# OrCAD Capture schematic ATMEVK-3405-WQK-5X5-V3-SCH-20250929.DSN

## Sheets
1 10. VDDIO-VCCIO Tracking: size B; title: ATM3405 EVALUATION BOARD; rev: 3; note: 085-37-510-xxxx
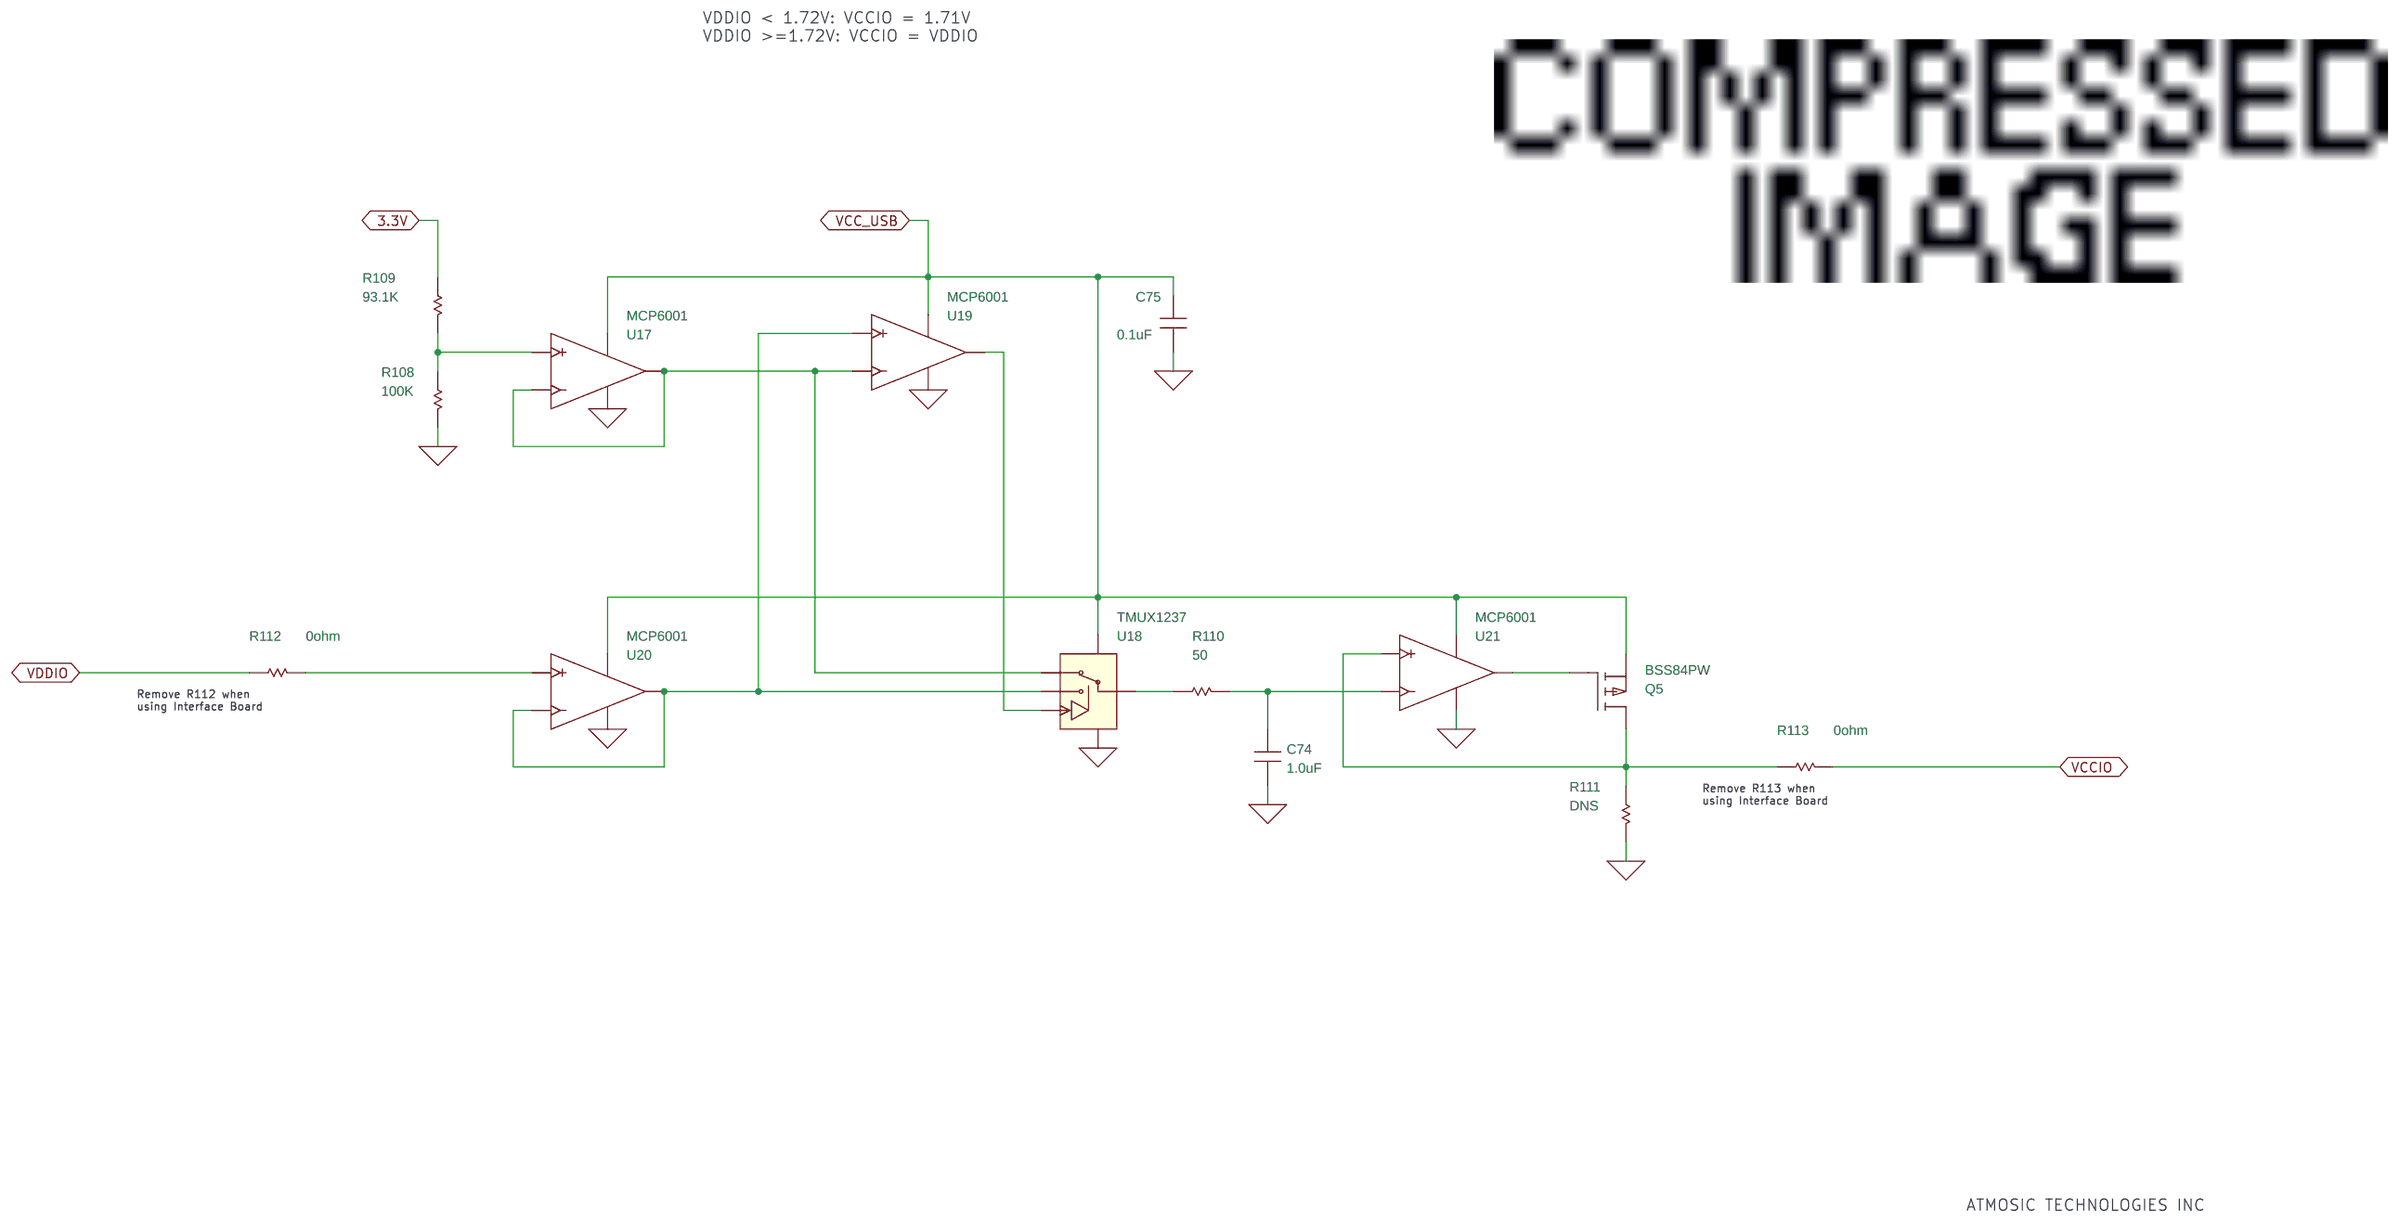
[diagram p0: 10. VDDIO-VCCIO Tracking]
2 01. TITLE
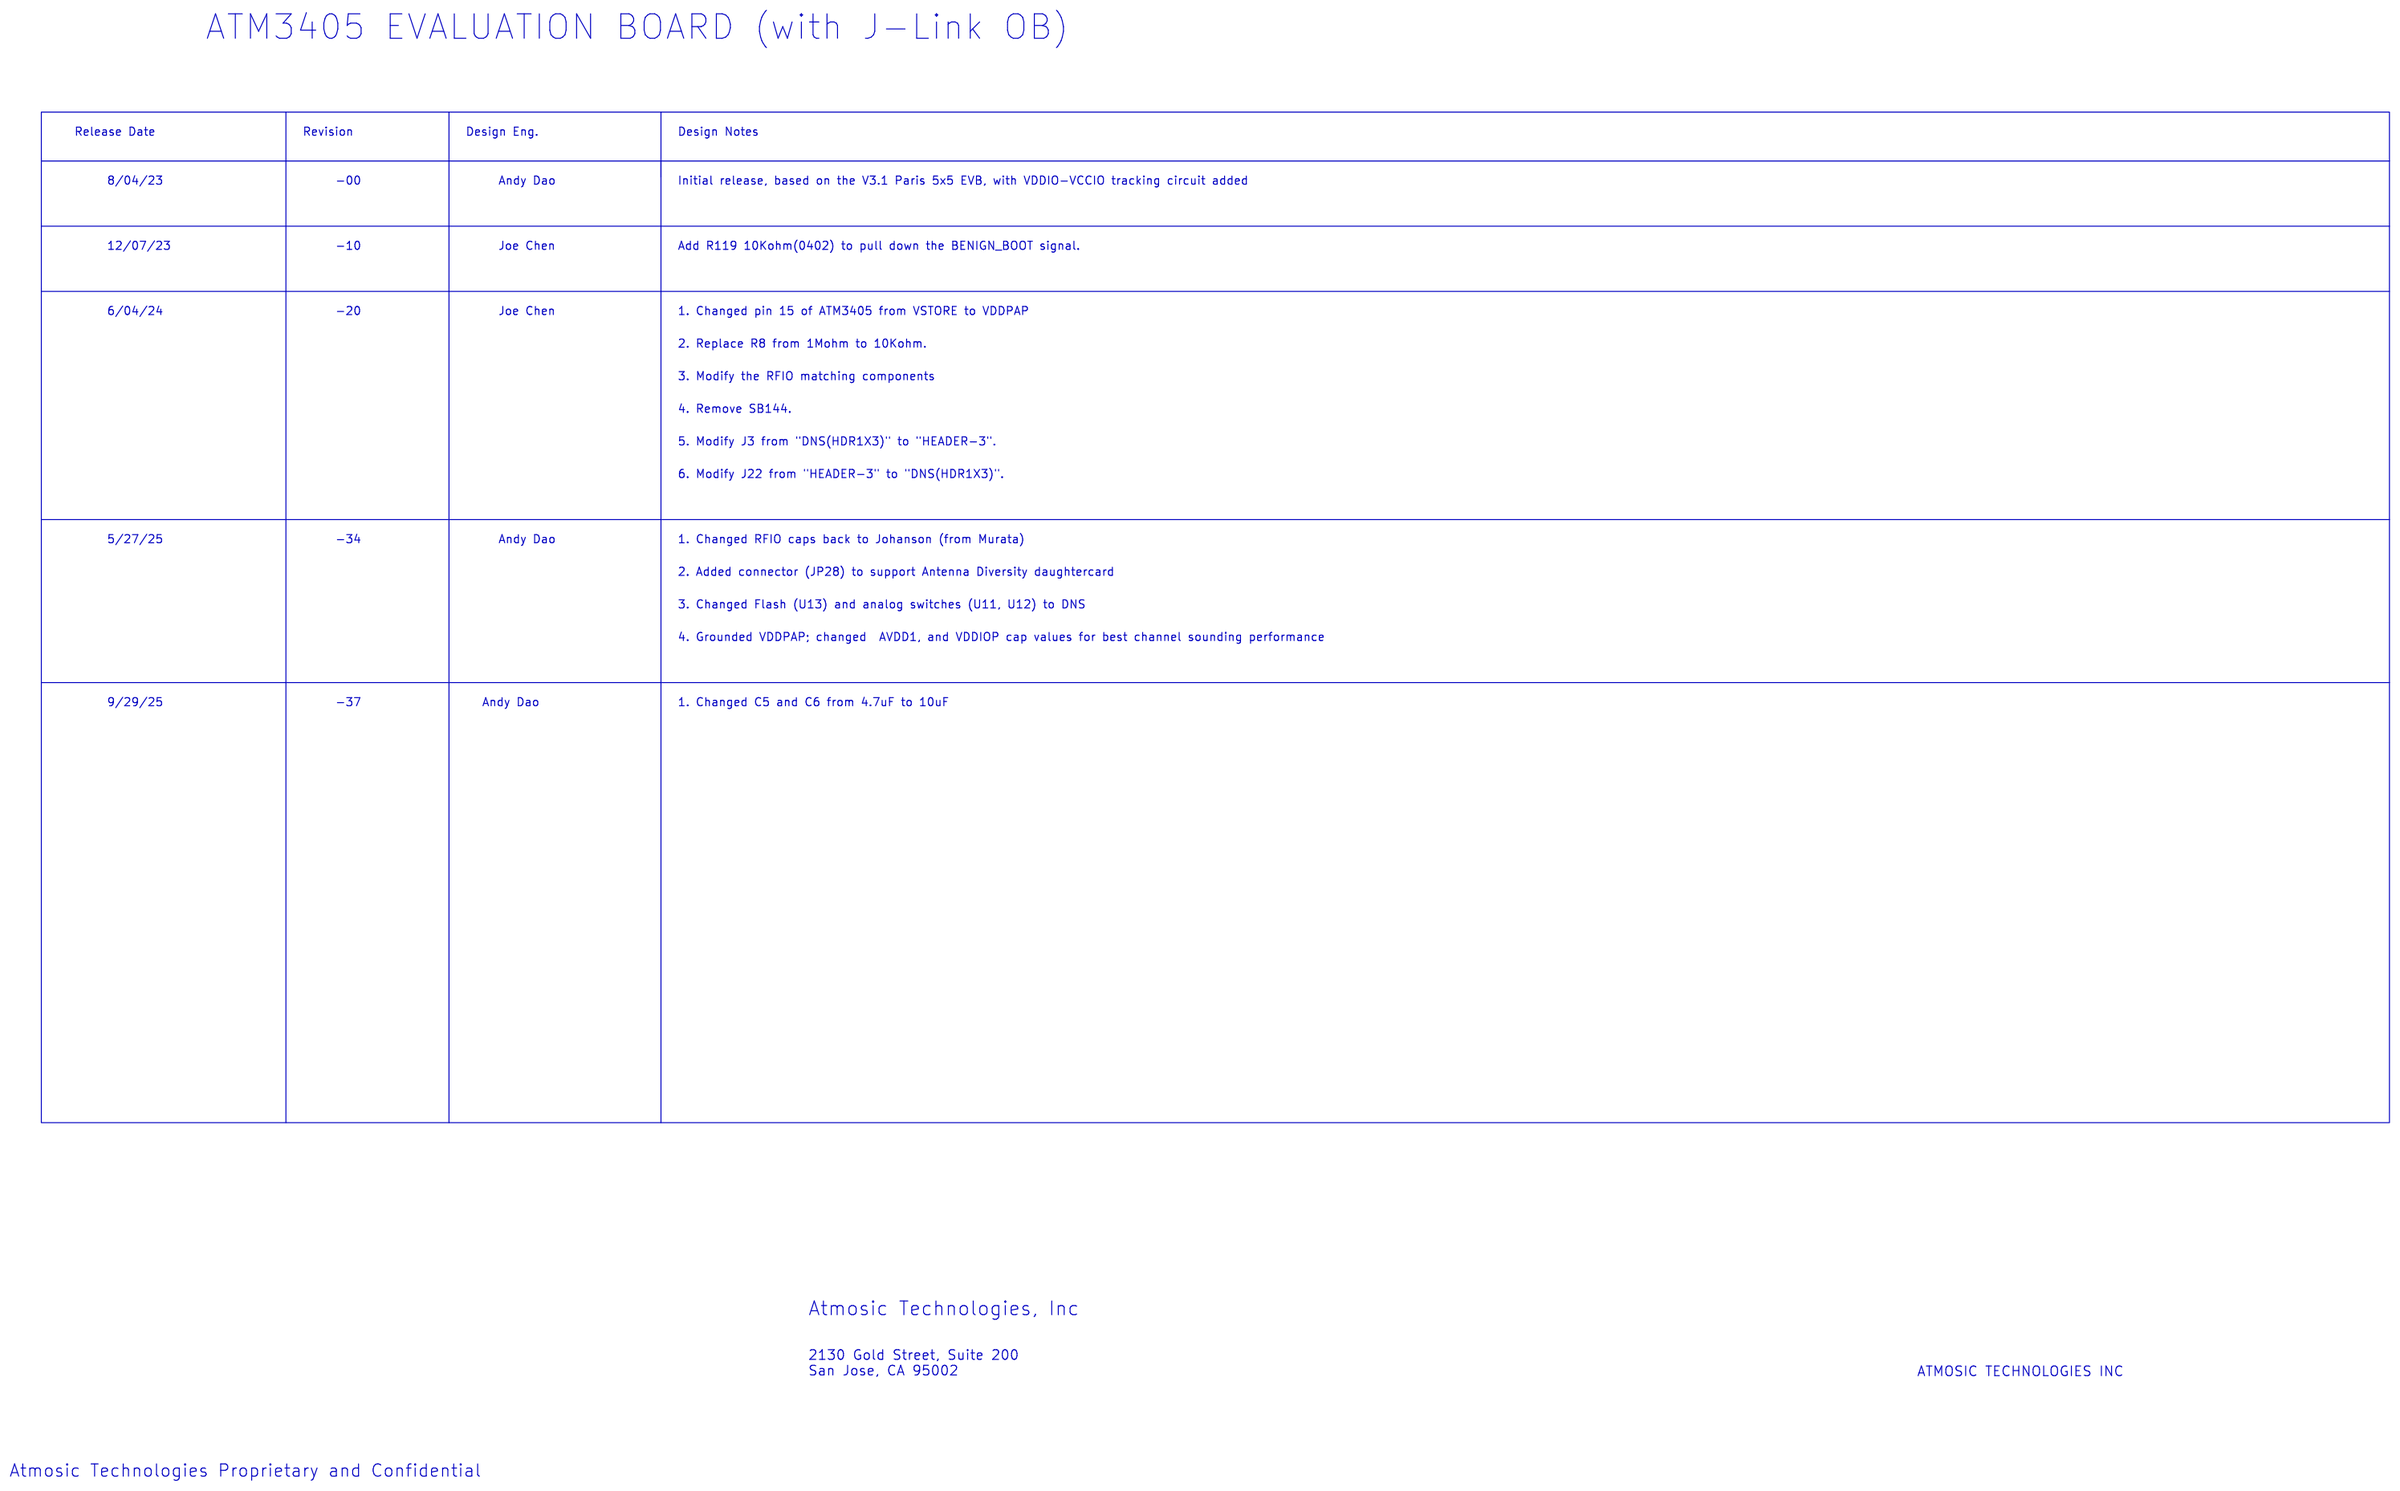
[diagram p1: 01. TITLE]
3 02. Block Diagram
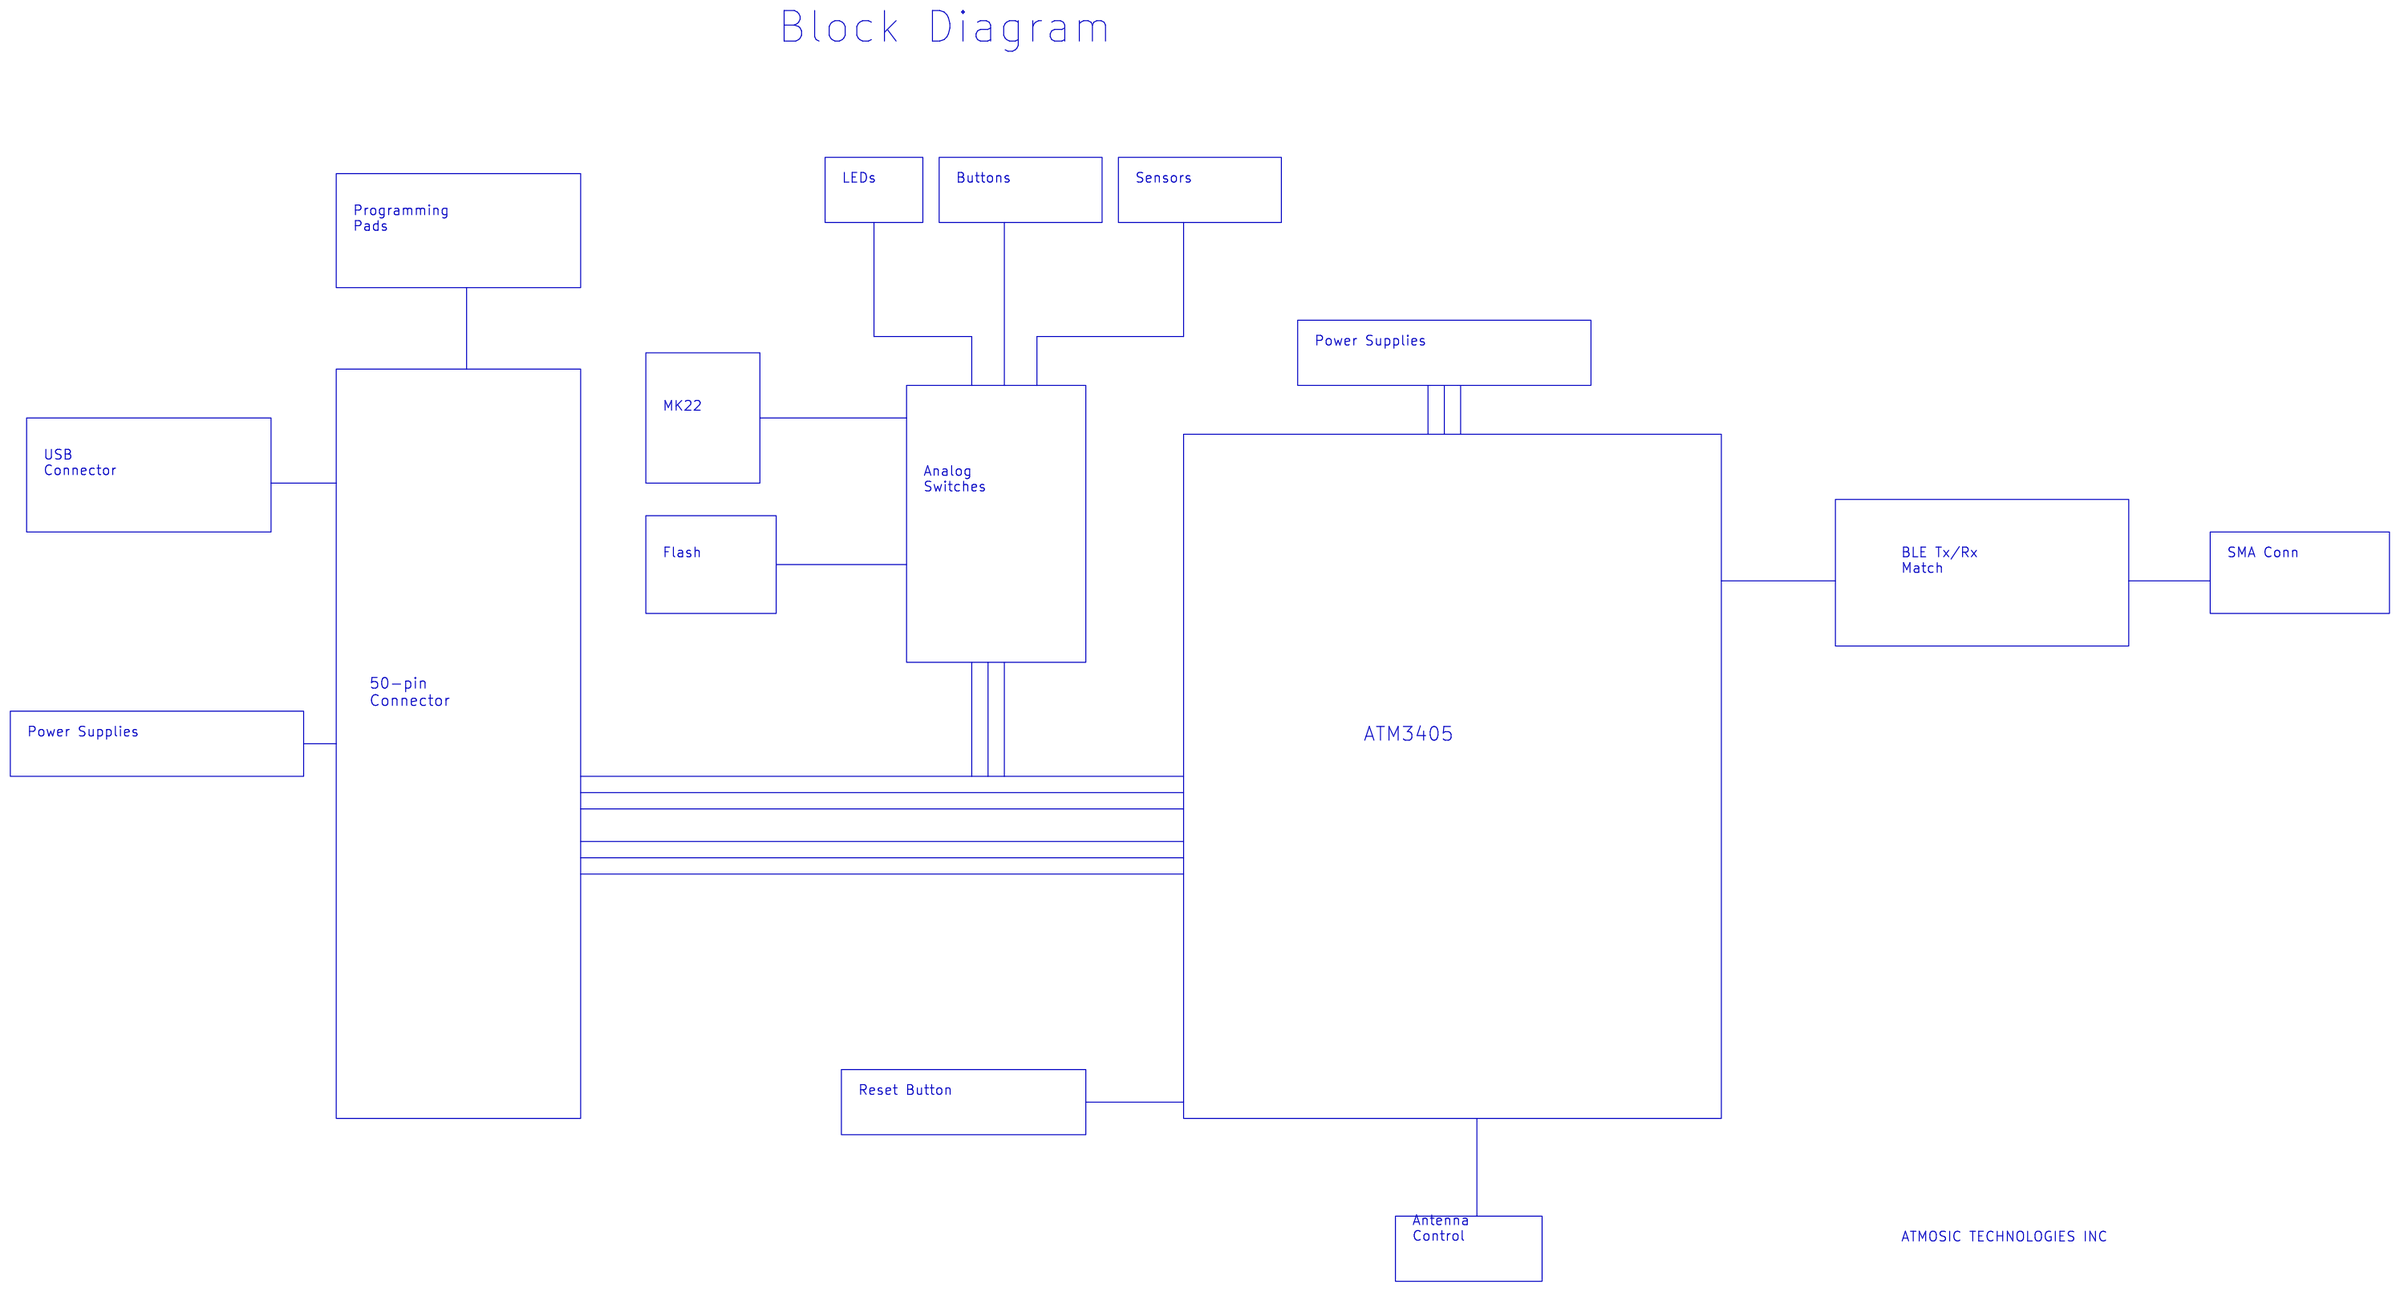
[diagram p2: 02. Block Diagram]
4 03. ATM3405: size B
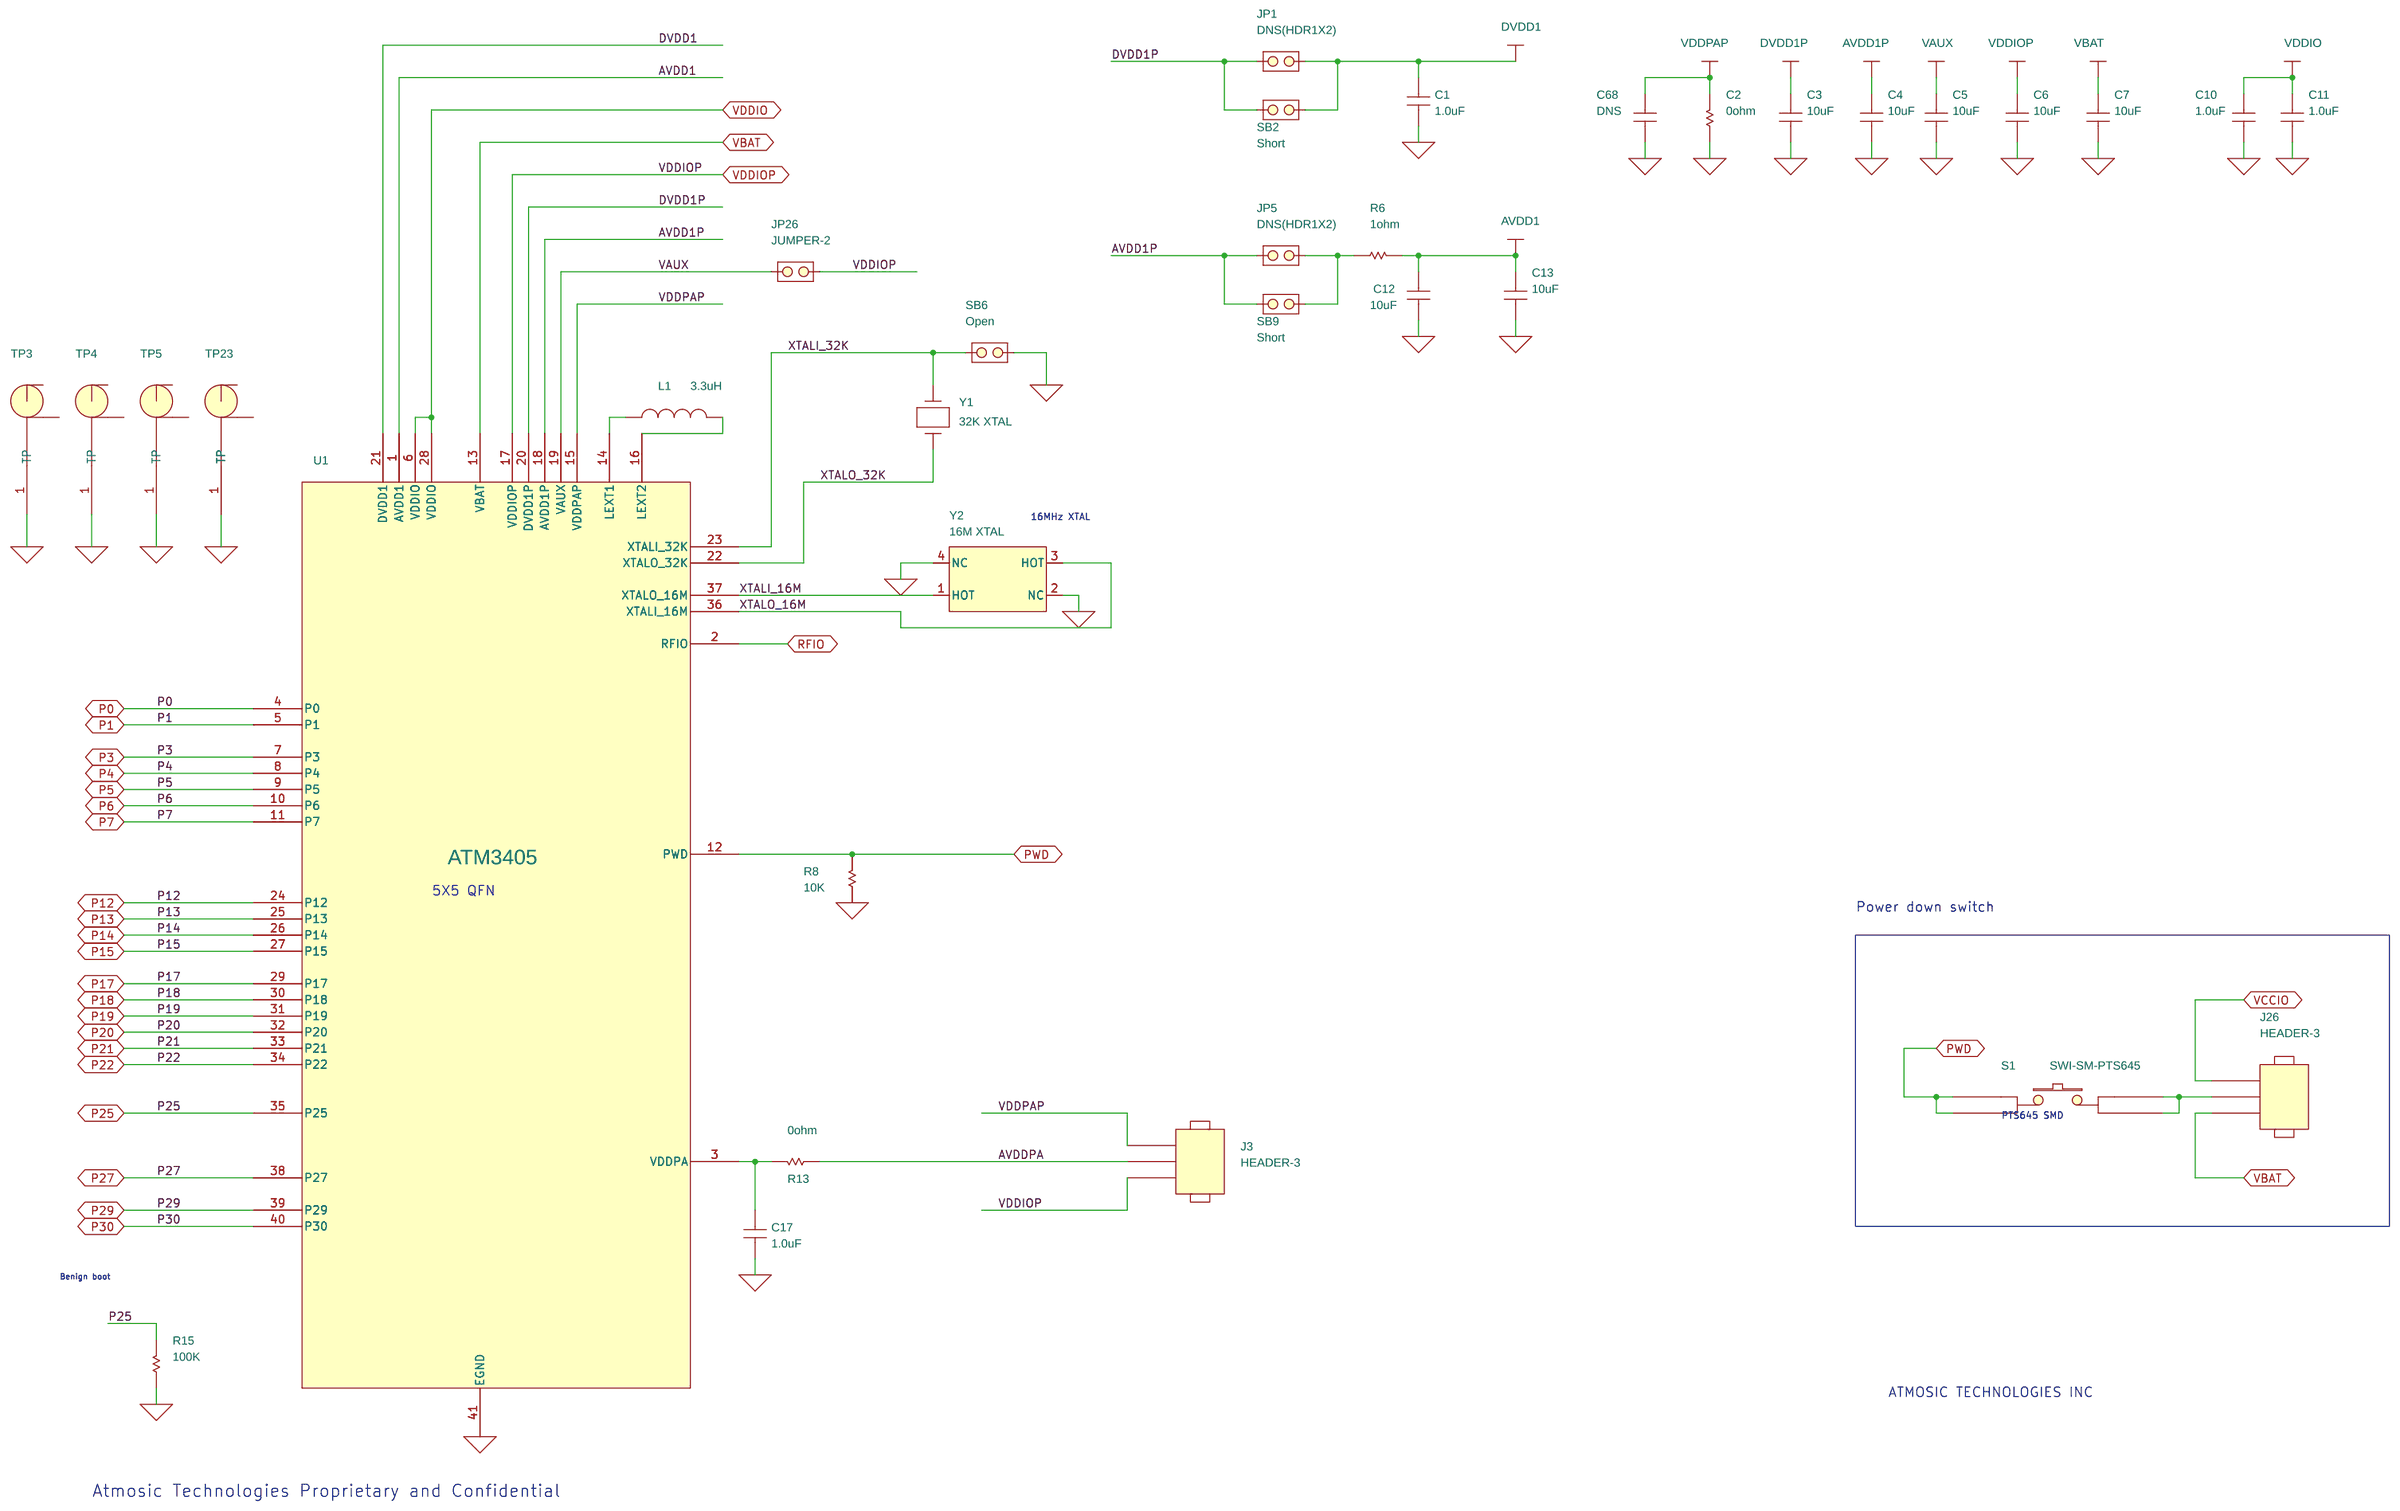
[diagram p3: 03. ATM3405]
5 04. GPIO Mapping: size B
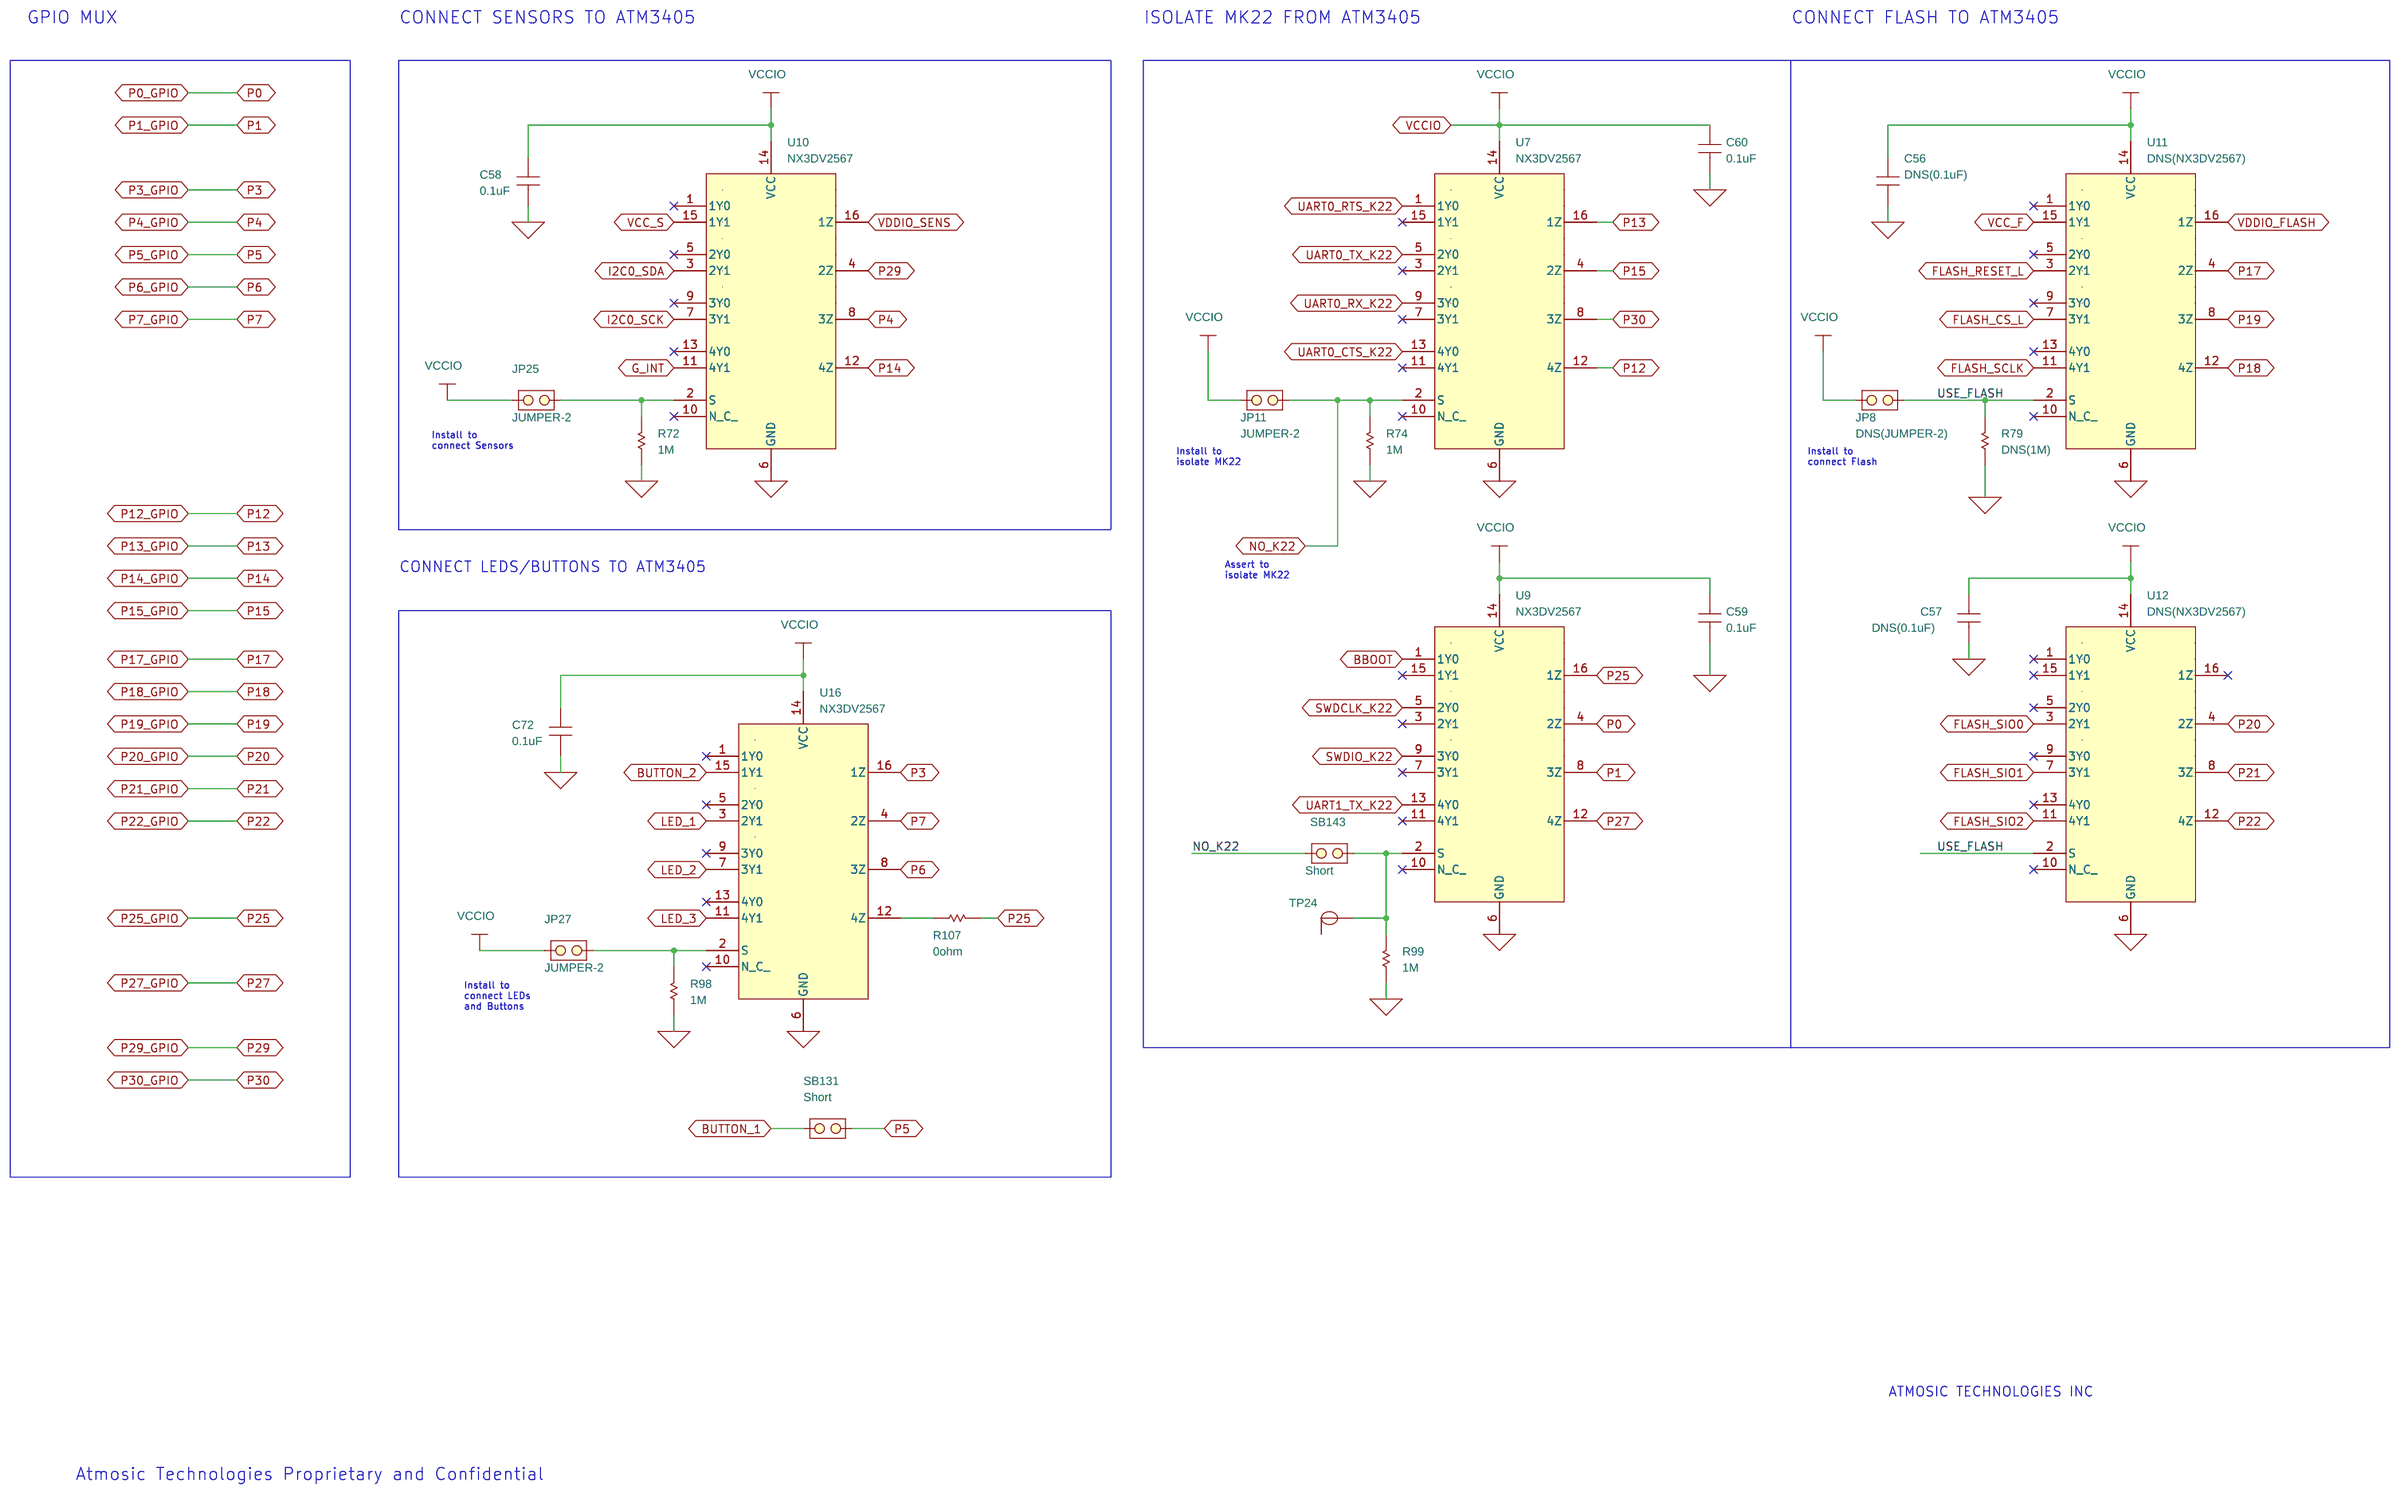
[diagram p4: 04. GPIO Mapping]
6 05. RF (RFIO): size B
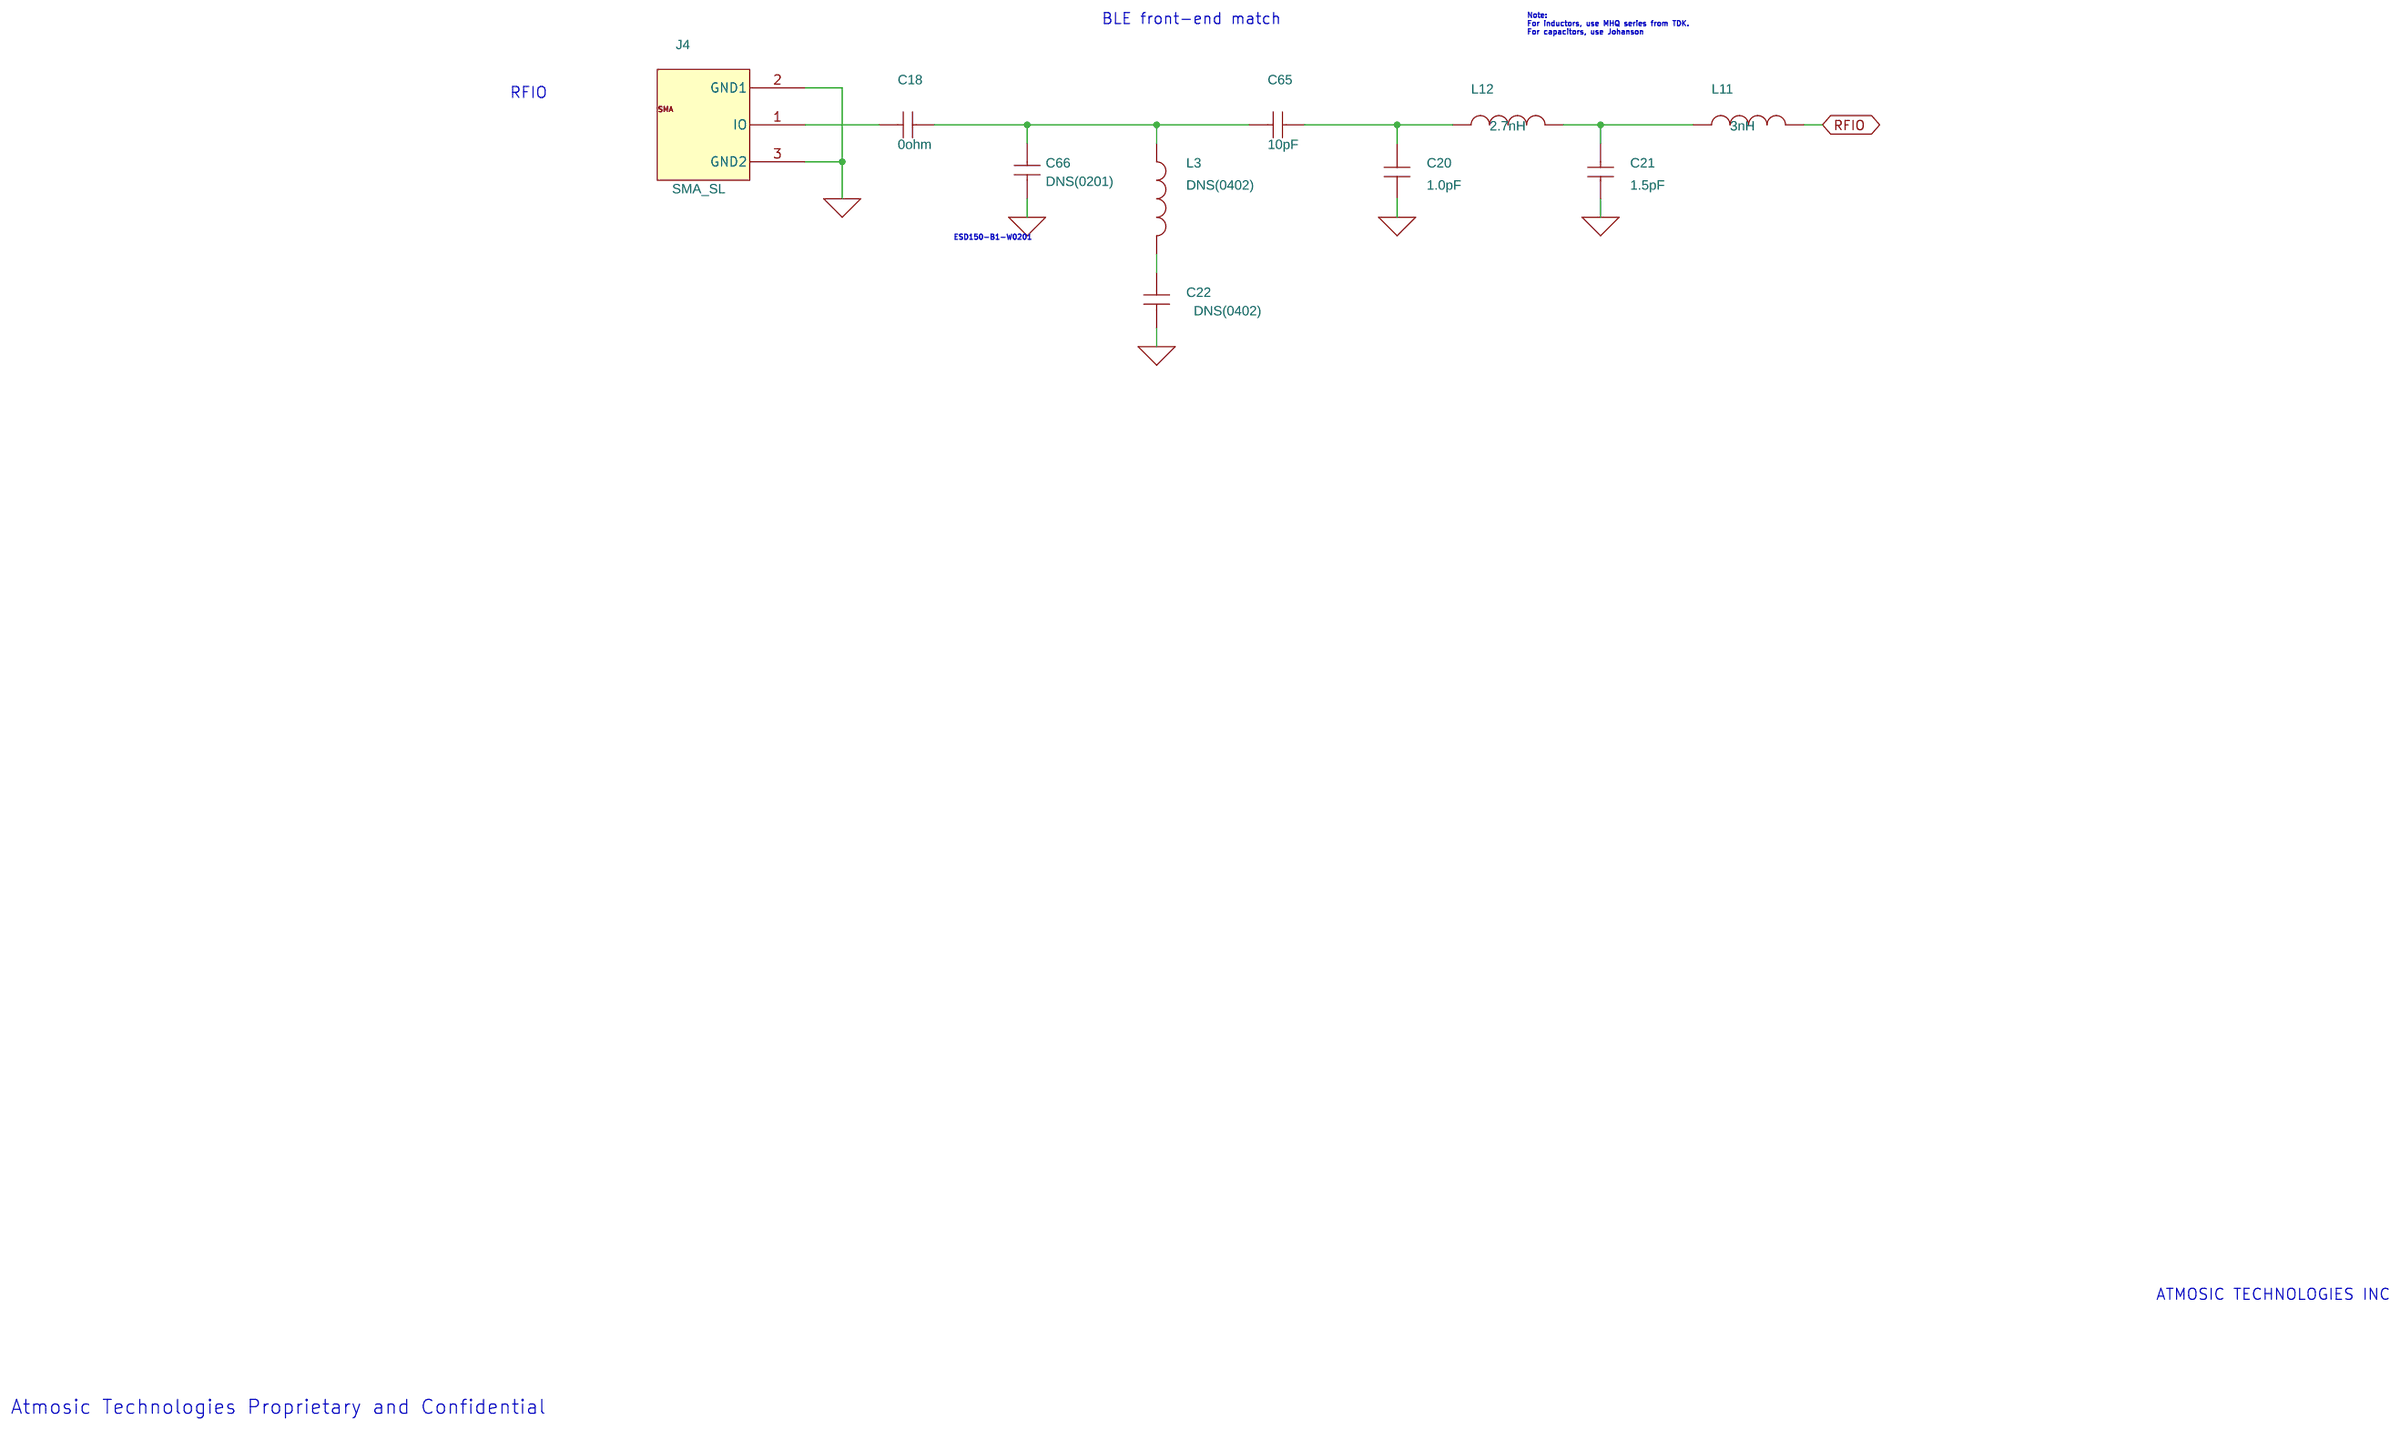
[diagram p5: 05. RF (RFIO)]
7 06. Buttons LEDs Sensors: size B
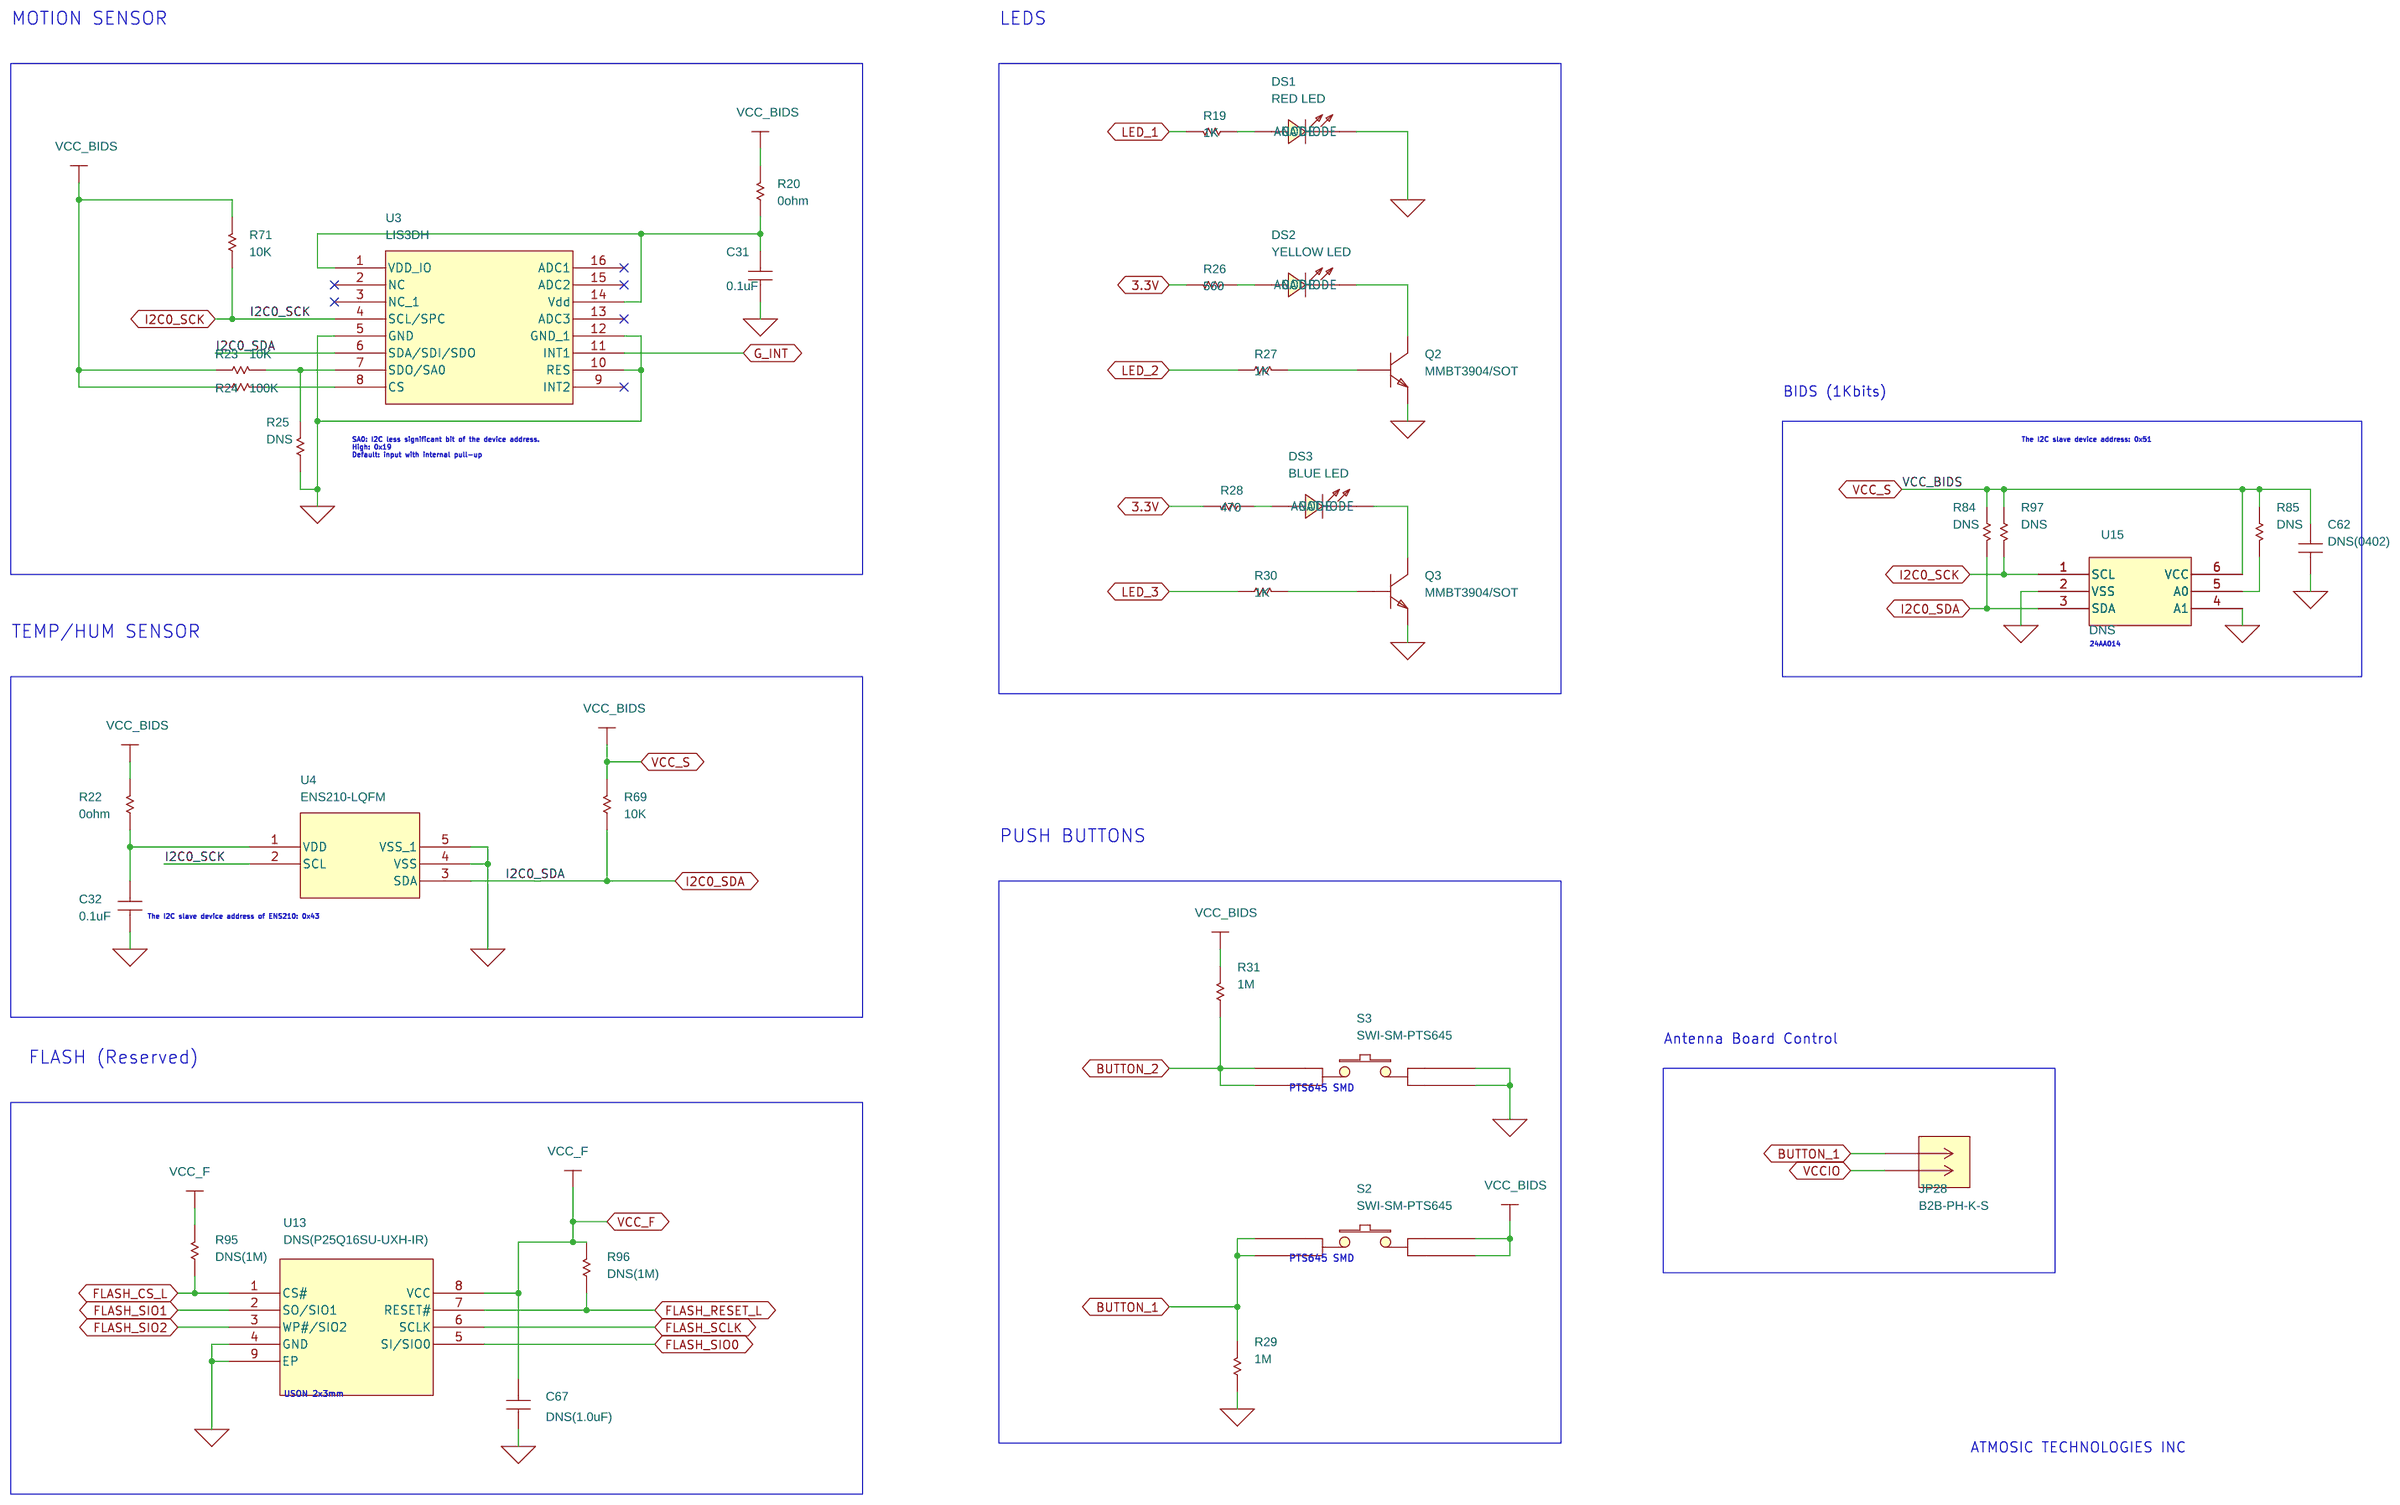
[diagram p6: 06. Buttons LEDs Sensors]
8 07. Connectors: size B
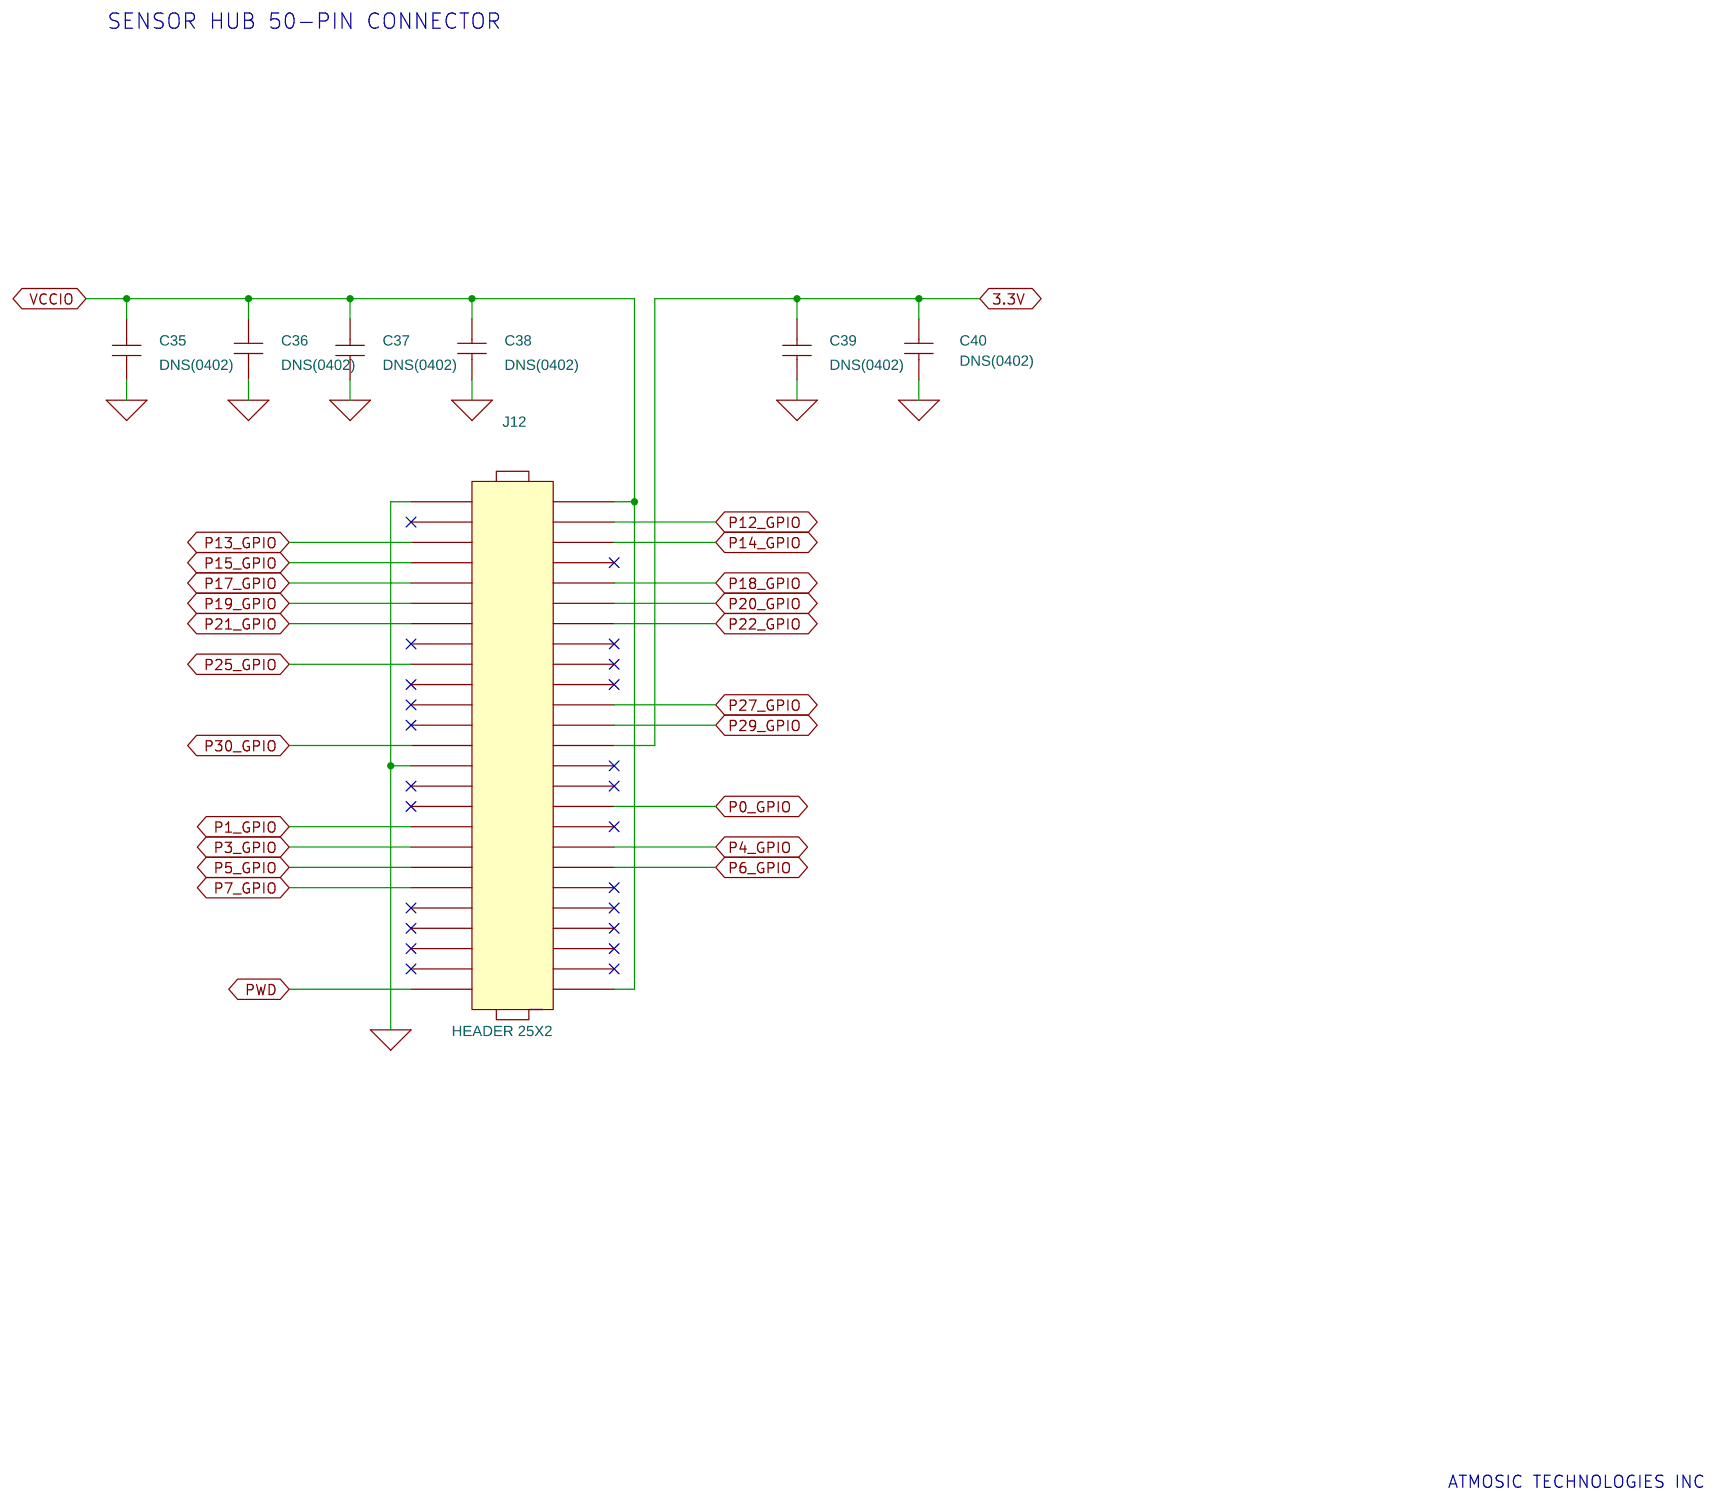
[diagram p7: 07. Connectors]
9 08. MK22: size B
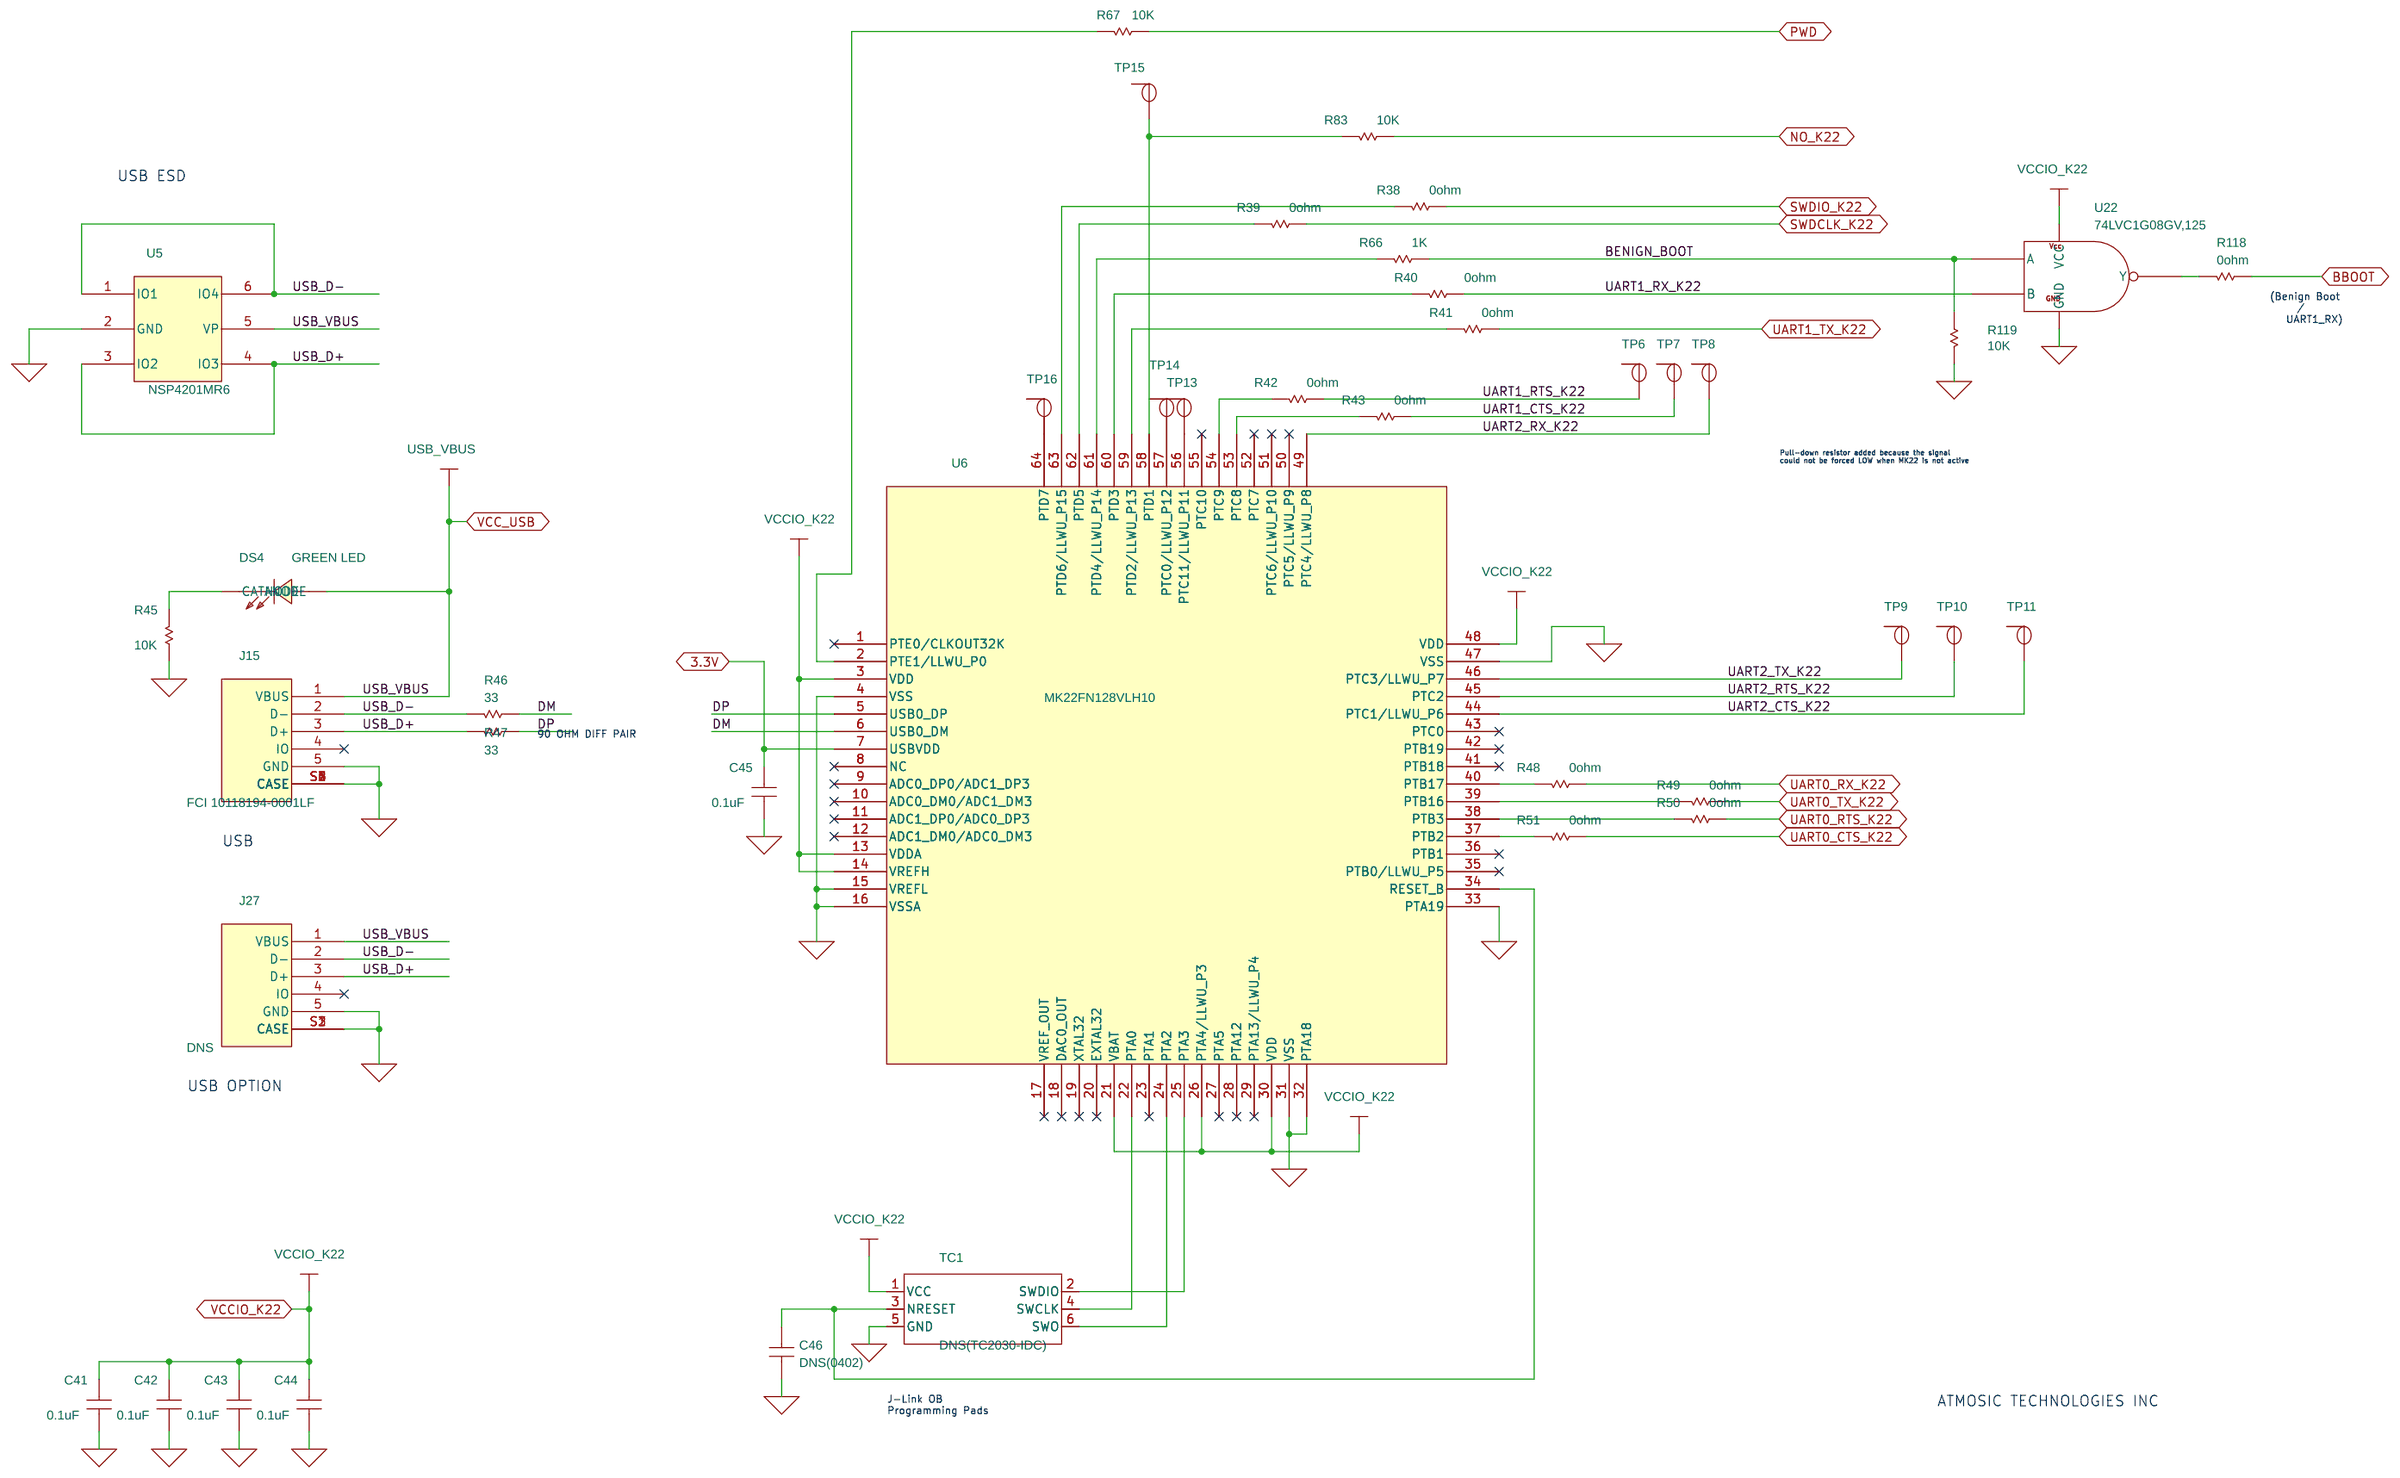
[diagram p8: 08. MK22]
10 09. Power: size B
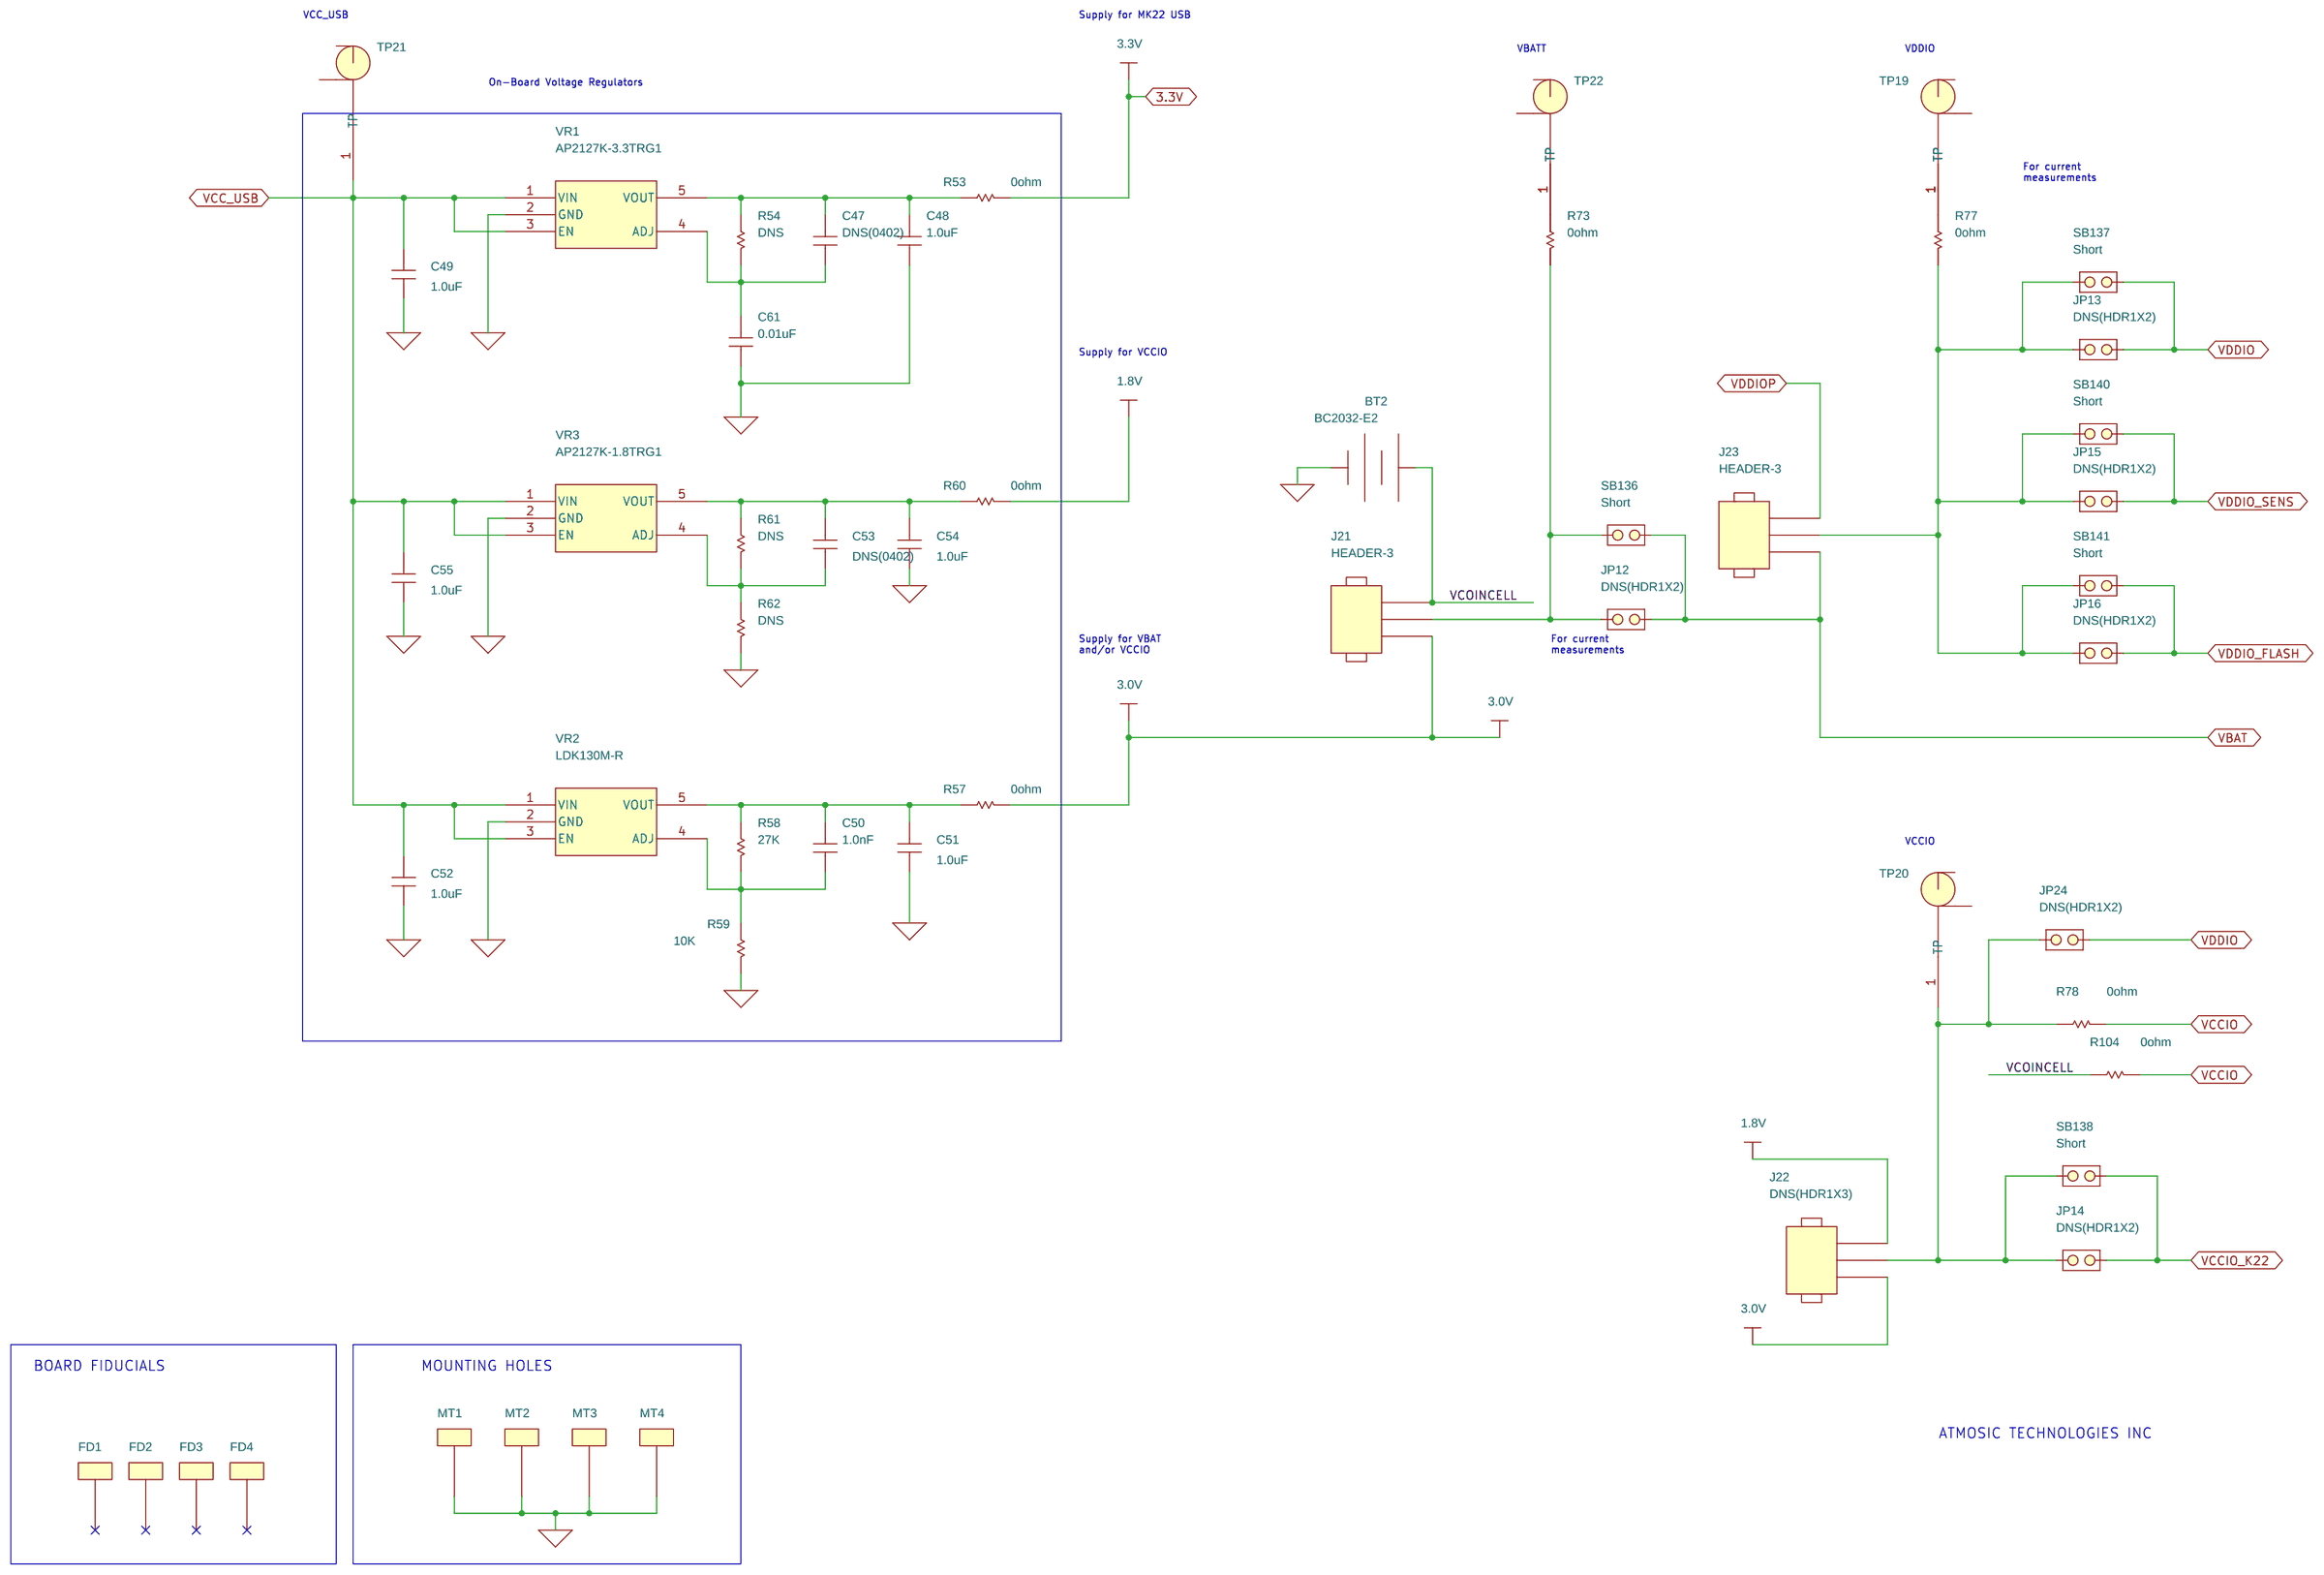
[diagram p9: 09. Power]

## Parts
sheet 03. ATM3405
C1  1.0uF  [0402]
C2  0ohm  [0402]
C3  10uF  [0402]
C4  10uF  [0402]
C5  10uF  [0402]
C6  10uF  [0402]
C7  10uF  [0402]
C10  1.0uF  [0402]
C11  1.0uF  [0402]
C12  10uF  [0603]
C13  10uF  [0603]
C17  1.0uF  [0402]
C68  DNS  [0402]
J3  HEADER-3  [HDR1X3]
J26  HEADER-3  [HDR1X3]
JP1  DNS(HDR1X2)  [HDR1X2]
JP5  DNS(HDR1X2)  [HDR1X2]
JP26  JUMPER-2  [HDR1X2]
L1  3.3uH  [L_DFE252012F]
R6  1ohm  [0402]
R8  10K  [0402]
R13  0ohm  [0402]
R15  100K  [0402]
S1  SWI-SM-PTS645  [SWI-SM-PTS645]
SB2  Short  [SB]
SB6  Open  [SB]
SB9  Short  [SB]
TP3  TP-BLK  [TESTPIN]
TP4  TP-BLK  [TESTPIN]
TP5  TP-BLK  [TESTPIN]
TP23  TP-BLK  [TESTPIN]
U1  ATM3405  [QFN-40-5X5-0.4MM]
Y1  32K XTAL  [XTAL-SMD2-2.0X1.2MM]
Y2  16M XTAL  [XTAL-ECX-2236]
sheet 04. GPIO Mapping
C56  DNS(0.1uF)  [0402]
C57  DNS(0.1uF)  [0402]
C58  0.1uF  [0402]
C59  0.1uF  [0402]
C60  0.1uF  [0402]
C72  0.1uF  [0402]
JP8  DNS(JUMPER-2)  [HDR1X2]
JP11  JUMPER-2  [HDR1X2]
JP25  JUMPER-2  [HDR1X2]
JP27  JUMPER-2  [HDR1X2]
R72  1M  [0402]
R74  1M  [0402]
R79  DNS(1M)  [0402]
R98  1M  [0402]
R99  1M  [0402]
R107  0ohm  [0402]
SB131  Short  [SB]
SB143  Short  [SB]
TP24  TP  [TESTPAD50]
U7  NX3DV2567  [XQFN16]
U9  NX3DV2567  [XQFN16]
U10  NX3DV2567  [XQFN16]
U11  DNS(NX3DV2567)  [XQFN16]
U12  DNS(NX3DV2567)  [XQFN16]
U16  NX3DV2567  [XQFN16]
sheet 05. RF (RFIO)
C18  0ohm  [0402]
C20  1.0pF  [0402]
C21  1.5pF  [0402]
C22  DNS(0402)  [0402]
C65  10pF  [0402]
C66  DNS(0201)  [0201]
J4  SMA_SL  [SMA-RA]
L3  DNS(0402)  [0402]
L11  3nH  [0402]
L12  2.7nH  [0402]
sheet 06. Buttons LEDs Sensors
C31  0.1uF  [0402]
C32  0.1uF  [0402]
C62  DNS(0402)  [0402]
C67  DNS(1.0uF)  [0402]
DS1  RED LED  [LED-0603]
DS2  YELLOW LED  [LED-0603]
DS3  BLUE LED  [LED-0603]
JP28  B2B-PH-K-S  [CON_B2B_PH_K_SLFSN_JST]
Q2  MMBT3904/SOT  [TRA-SOT23]
Q3  MMBT3904/SOT  [TRA-SOT23]
R19  1K  [0402]
R20  0ohm  [0402]
R22  0ohm  [0402]
R23  10K  [0402]
R24  100K  [0402]
R25  DNS  [0402]
R26  560  [0402]
R27  1K  [0402]
R28  470  [0402]
R29  1M  [0402]
R30  1K  [0402]
R31  1M  [0402]
R69  10K  [0402]
R71  10K  [0402]
R84  DNS  [0402]
R85  DNS  [0402]
R95  DNS(1M)  [0402]
R96  DNS(1M)  [0402]
R97  DNS  [0402]
S2  SWI-SM-PTS645  [SWI-SM-PTS645]
S3  SWI-SM-PTS645  [SWI-SM-PTS645]
U3  LIS3DH  [LGA-16-3X3]
U4  ENS210-LQFM  [SON-04-2X2MM]
U13  DNS(P25Q16SU-UXH-IR)  [USON-8-2X3-EP]
U15  DNS  [SOT23-6]
sheet 07. Connectors
C35  DNS(0402)  [0402]
C36  DNS(0402)  [0402]
C37  DNS(0402)  [0402]
C38  DNS(0402)  [0402]
C39  DNS(0402)  [0402]
C40  DNS(0402)  [0402]
J12  HEADER 25X2  [HDR25X2]
sheet 08. MK22
C41  0.1uF  [0402]
C42  0.1uF  [0402]
C43  0.1uF  [0402]
C44  0.1uF  [0402]
C45  0.1uF  [0402]
C46  DNS(0402)  [0402]
DS4  GREEN LED  [LED-0603]
J15  FCI 10118194-0001LF  [10118194-0001LF]
J27  DNS  [MOLEX-105133-0031]
R38  0ohm  [0402]
R39  0ohm  [0402]
R40  0ohm  [0402]
R41  0ohm  [0402]
R42  0ohm  [0402]
R43  0ohm  [0402]
R45  10K  [0402]
R46  33  [0402]
R47  33  [0402]
R48  0ohm  [0402]
R49  0ohm  [0402]
R50  0ohm  [0402]
R51  0ohm  [0402]
R66  1K  [0402]
R67  10K  [0402]
R83  10K  [0402]
R118  0ohm  [0402]
R119  10K  [0402]
TC1  DNS(TC2030-IDC)  [CON-TC2030-IDC]
TP6  TP  [TESTPAD50]
TP7  TP  [TESTPAD50]
TP8  TP  [TESTPAD50]
TP9  TP  [TESTPAD50]
TP10  TP  [TESTPAD50]
TP11  TP  [TESTPAD50]
TP13  TP  [TESTPAD50]
TP14  TP  [TESTPAD50]
TP15  TP  [TESTPAD50]
TP16  TP  [TESTPAD50]
U5  NSP4201MR6  [TSOP-6]
U6  MK22FN128VLH10  [LQFP-64-10X10-0.5MM]
U22  74LVC1G08GV,125  [SOT23-5]
sheet 09. Power
BT2  BC2032-E2  [BAT-HOLDER-2032]
C47  DNS(0402)  [0402]
C48  1.0uF  [0402]
C49  1.0uF  [0402]
C50  1.0nF  [0402]
C51  1.0uF  [0402]
C52  1.0uF  [0402]
C53  DNS(0402)  [0402]
C54  1.0uF  [0402]
C55  1.0uF  [0402]
C61  0.01uF  [0402]
FD1  TEST POINT  [FID-G]
FD2  TEST POINT  [FID-G]
FD3  TEST POINT  [FID-G]
FD4  TEST POINT  [FID-G]
J21  HEADER-3  [HDR1X3]
J22  DNS(HDR1X3)  [HDR1X3]
J23  HEADER-3  [HDR1X3]
JP12  DNS(HDR1X2)  [HDR1X2]
JP13  DNS(HDR1X2)  [HDR1X2]
JP14  DNS(HDR1X2)  [HDR1X2]
JP15  DNS(HDR1X2)  [HDR1X2]
JP16  DNS(HDR1X2)  [HDR1X2]
JP24  DNS(HDR1X2)  [HDR1X2]
MT1  TEST POINT  [HOLE-250R125]
MT2  TEST POINT  [HOLE-250R125]
MT3  TEST POINT  [HOLE-250R125]
MT4  TEST POINT  [HOLE-250R125]
R53  0ohm  [0402]
R54  DNS  [0402]
R57  0ohm  [0402]
R58  27K  [0402]
R59  10K  [0402]
R60  0ohm  [0402]
R61  DNS  [0402]
R62  DNS  [0402]
R73  0ohm  [0402]
R77  0ohm  [0402]
R78  0ohm  [0402]
R104  0ohm  [0402]
SB136  Short  [SB]
SB137  Short  [SB]
SB138  Short  [SB]
SB140  Short  [SB]
SB141  Short  [SB]
TP19  TP-WHT  [TESTPIN]
TP20  TP-WHT  [TESTPIN]
TP21  TP-WHT  [TESTPIN]
TP22  TP-WHT  [TESTPIN]
VR1  AP2127K-3.3TRG1  [SOT23-5]
VR2  LDK130M-R  [SOT23-5]
VR3  AP2127K-1.8TRG1  [SOT23-5]
sheet 10. VDDIO-VCCIO Tracking
C74  1.0uF  [0402]
C75  0.1uF  [0402]
Q5  BSS84PW  [SOT-323]
R108  100K  [0402]
R109  93.1K  [0402]
R110  50  [0402]
R111  DNS  [0402]
R112  0ohm  [0402]
R113  0ohm  [0402]
U17  MCP6001  [SC70]
U18  TMUX1237  [SC70-6]
U19  MCP6001  [SC70]
U20  MCP6001  [SC70]
U21  MCP6001  [SC70]

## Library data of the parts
C1 C10 C11 C48 C49 C51 C52 C54 C55 C67 = SMALL_CAP: Manufacture_Name: MURATA; Manufacture_Part_Number: GRT155R61E105ME01D; Part Number: 01-2000007; Price: 0.003; Vendor: MURATA; Datasheet: https://www.digikey.com/product-detail/en/murata-electronics-north-america/GRT155R61E105ME01D/490-12264-1-ND/5416965
C2 R107 = SMALL_R1: Manufacture_Name: PANASONIC; Manufacture_Part_Number: ERJ-2GE0R00X; Part Number: 03-2000018; Price: 0.0002; Vendor: YAGEO; Datasheet: https://www.digikey.com/en/products/detail/panasonic-electronic-components/erj-2ge0r00x/146727
C3-C7 = SMALL_CAP: Manufacture_Name: MURATA; Manufacture_Part_Number: GRM155R60J106ME15D; Part Number: 01-2000011; Price: 0.00378; Vendor: MURATA; Datasheet: https://www.digikey.com/product-detail/en/murata-electronics-north-america/GRM155R60J106ME15D/490-13238-1-ND/5877446
C12 C13 = SMALL_CAP: Manufacture_Name: MURATA; Manufacture_Part_Number: GRM185R60J106ME15J; Part Number: 01-3000002; Price: 0.0038; Vendor: MURATA; Datasheet: https://www.digikey.com/en/products/detail/murata-electronics/GRM185R60J106ME15J/7363093
C17 C74 = SMALL_CAP: Manufacture_Name: MURATA; Manufacture_Part_Number: GRT155R61E105ME01D; Part Number: 01-2000007; Price: 0.003; Datasheet: https://www.digikey.com/product-detail/en/murata-electronics-north-america/GRT155R61E105ME01D/490-12264-1-ND/5416965
C31 C32 C41-C45 C56-C60 C68 C72 C75 = SMALL_CAP: Manufacture_Name: TAIYO-YUDEN; Manufacture_Part_Number: TMK105BJ104KV-F; Part Number: 01-2000003; Price: 0.0013; Vendor: TAIYO-YUDEN; Datasheet: https://www.digikey.com/en/products/detail/taiyo-yuden/TMK105BJ104KV-F/1004044
J3 = HEADER_3: Manufacture_Name: AMPHENOL ICC (FCI); Manufacture_Part_Number: 68000-103HLF; Part Number: 08-0000003; Datasheet: https://www.digikey.tw/en/products/detail/amphenol-cs-fci/68000-103HLF/2023309?s=N4IgTCBcDaIGwA4AMKC0BGJBmAEgGQDEQBdAXyA
J21 J23 J26 = HEADER_3: Manufacture_Name: AMPHENOL ICC (FCI); Manufacture_Part_Number: 68000-103HLF; Part Number: 08-0000003; Vendor: AMPHENOL ICC (FCI); Datasheet: https://www.digikey.tw/en/products/detail/amphenol-cs-fci/68000-103HLF/2023309?s=N4IgTCBcDaIGwA4AMKC0BGJBmAEgGQDEQBdAXyA
JP1 JP5 JP12-JP16 JP24 = JUMPER-2: Part Number: 08-0000019
JP8 JP11 JP25-JP27 = JUMPER-2: Manufacture_Name: AMPHENOL ICC (FCI); Manufacture_Part_Number: 68000-102HLF; Part Number: 08-0000002; Price: 0.0066; Vendor: AMPHENOL ICC (FCI); Datasheet: https://www.digikey.com/products/en?keywords=68000-102HLF
L1 = INDUCTOR: Manufacture_Name: MURATA; Manufacture_Part_Number: LQM2MPN3R3NG0L; Part Number: 02-4000013; Price: 0.025; Datasheet: https://www.digikey.com/en/products/detail/murata-electronics/LQM2MPN3R3NG0L/4359169?s=N4IgTCBcDaIDoBcAEAZAigWTBgCgOwGYAlAgOQHEAGFEAXQF8g
R6 = SMALL_R1: Manufacture_Name: YAGEO; Manufacture_Part_Number: RC0402FR-071RL; Part Description: RES 1 OHM 1% 1/16W 0402; Part Number: 03-2000032; Price: 0.0002; Vendor: YAGEO; Datasheet: https://www.digikey.com/product-detail/en/yageo/RC0402FR-071RL/311-1.00LRCT-ND/729461
R8 R23 R45 R59 R67 R69 R83 = SMALL_R1: Manufacture_Name: YAGEO; Manufacture_Part_Number: RC0402JR-0710KL; Part Number: 03-2000021; Price: 0.0002; Vendor: YAGEO; Datasheet: https://www.digikey.com/en/products/detail/yageo/RC0402JR-0710KL/726418
R13 R20 R22 R38 R39 R41-R43 R48-R51 R53 R57 R60 R73 R77 R78 R104 = SMALL_R1: Manufacture_Name: PANASONIC; Manufacture_Part_Number: ERJ-2GE0R00X; Part Number: 03-2000018; Price: 0.0002; Vendor: PANASONIC; Datasheet: https://www.digikey.com/en/products/detail/panasonic-electronic-components/erj-2ge0r00x/146727
R15 R24 = SMALL_R1: Manufacture_Name: YAGEO; Manufacture_Part_Number: RC0402JR-07100KL; Part Number: 03-2000020; Price: 0.0002; Vendor: YAGEO; Datasheet: https://www.digikey.com/en/products/detail/yageo/RC0402JR-07100KL/726416
S1-S3 = SW-TACT-4P-5: Manufacture_Name: C&K; Manufacture_Part_Number: PTS645SK50SMTR92 LFS; Part Number: 07-0000027; Datasheet: https://www.digikey.com/product-detail/en/c-k/PTS645SK50SMTR92-LFS/CKN9087CT-ND/1146813
SB2 SB9 SB131 SB136-SB138 SB140 SB141 SB143 = SB: Part Number: 03-1000004
SB6 = SB: Part Number: 03-1000006
TP3-TP5 TP23 = TP: Manufacture_Name: KEYSTONE ELECTRONICS; Manufacture_Part_Number: 36-5011-ND; Part Number: 08-0000006; Vendor: KEYSTONE ELECTRONICS; Datasheet: https://www.digikey.com/product-detail/en/keystone-electronics/5011/36-5011-ND/255333
U1 = PERTH_ATM3425_QFN5X5: Manufacture_Name: Atmosic; Manufacture_Part_Number: ATM3405-5WCAQK; Part Description: ATM3405, QFN-40-5x5-0.4MM, 512K/256K; Part Number: 04-0000010
Y1 = XTAL: Manufacture_Name: SEIKO; Manufacture_Part_Number: SC20S-7PF20PPM; Part Number: 06-0000018; Price: 0.065; Vendor: SEIKO; Datasheet: https://www.digikey.com/short/797qhnc0
Y2 = XTAL-OSC-4P_0: Manufacture_Name: Hosonic; Manufacture_Part_Number: E1SB16E00001KE; Part Number: 06-0000075; Price: 0.043; Datasheet: https://drive.google.com/drive/folders/1THAUNzENGgR3SJ0kmd_V7woV18_ClvpD
R29 R31 R72 R74 R79 R95 R96 R98 R99 = SMALL_R1: Manufacture_Name: YAGEO; Manufacture_Part_Number: RC0402JR-071ML; Part Number: 03-2000030; Price: 0.0002; Vendor: YAGEO; Datasheet: https://www.digikey.com/product-detail/en/yageo/RC0402JR-071ML/311-1.0MJRCT-ND/729356
TP6-TP11 TP13-TP16 TP24 = TP_0: Part Number: 09-0000005
U7 U9-U12 U16 = NX3DV2567: Manufacture_Name: NXP; Manufacture_Part_Number: NX3DV2567GU115; Part Number: 05-0000007; Vendor: NXP; Datasheet: https://www.mouser.com/ProductDetail/NXP-Semiconductors/NX3DV2567GU115?qs=67TfscD5Pafw%252BgjlE0rl%2Fg%3D%3D
C18 = SMALL_CAP: Manufacture_Name: PANASONIC; Manufacture_Part_Number: ERJ-2GE0R00X; Part Number: 01-2000027; Price: 0.0002; Vendor: PANASONIC; Datasheet: https://www.digikey.com/en/products/detail/panasonic-electronic-components/erj-2ge0r00x/146727
C20 = SMALL_CAP: Manufacture_Name: JOHANSON; Manufacture_Part_Number: 500R07S1R0BV4T; Part Number: 01-2000006; Price: 0.001; Vendor: JOHANSON; Datasheet: https://www.digikey.com/en/products/detail/johanson-technology-inc/500R07S1R0BV4T/1561521?s=N4IgTCBcDaIKwAYECUEHYDKBGVAhAagCwAqIAugL5A
C21 = SMALL_CAP: Manufacture_Name: JOHANSON; Manufacture_Part_Number: QSCF500Q1R5B1GV001T; Part Description: CAP CER 1.5PF 50V C0G/NP0 0402; Part Number: 01-2000035; Price: 0.001; Vendor: JOHANSON; Datasheet: https://www.digikey.com/en/products/detail/johanson-technology-inc/QSCF500Q1R5B1GV001T/1561525?s=N4IgTCBcDaIDoBcAEBWADGgSmg7AZQEZMUAhANQBYAVEAXQF8g
C22 C35-C40 C46 C47 C53 C62 = SMALL_CAP: Part Number: 01-2000016
C65 = SMALL_CAP: Manufacture_Name: JOHANSON; Manufacture_Part_Number: 500R07S100JV4T; Part Number: 01-2000010; Price: 0.001; Vendor: JOHANSON; Datasheet: https://www.digikey.com/en/products/detail/johanson-technology-inc/500R07S100JV4T/1786715
C66 = SMALL_CAP: Part Number: 01-1000002
J4 = SMA_SL: Manufacture_Name: CINCH CONNECTIVITY SOLUTIONS JOHNSON; Manufacture_Part_Number: 142-0701-801; Part Number: 08-0000005; Price: 1.03; Vendor: CINCH CONNECTIVITY SOLUTIONS JOHNSON; Datasheet: https://www.digikey.com/product-detail/en/cinch-connectivity-solutions-johnson/142-0701-801/J502-ND/35280
L3 = INDUCTOR: Part Number: 02-2000004
L11 = INDUCTOR: Manufacture_Name: TDK; Manufacture_Part_Number: MHQ1005P3N0BT000; Part Description: FIXED IND 3.0NH ±0.1nH 900MA 80 MOHM SMD; Part Number: 02-2000021; Price: 0.0035; Vendor: TDK; Datasheet: https://www.digikey.com/en/products/detail/tdk-corporation/MHQ1005P3N0BT000/4742526?s=N4IgTCBcDaILIAkCKBGADGgrABQMwDk0AhAFQzRAF0BfIA
L12 = INDUCTOR: Manufacture_Name: TDK; Manufacture_Part_Number: MHQ1005P2N7BT000; Part Description: FIXED IND 2.7NH ±0.1nH 1A 70 MOHM SMD; Part Number: 02-2000002; Price: 0.0035; Vendor: TDK; Datasheet: https://www.digikey.com/en/products/detail/tdk-corporation/mhq1005p2n7bt000/4742525
DS1 = LED: Manufacture_Name: WURTH ELEKTRONIK; Manufacture_Part_Number: 150060RS75000; Part Number: 06-0000016; Price: 0.0083; Vendor: WURTH ELEKTRONIK; Datasheet: https://www.digikey.com/en/products/detail/w%C3%BCrth-elektronik/150060RS75000/4489901
DS2 = LED: Manufacture_Name: WURTH ELEKTRONIK; Manufacture_Part_Number: 150060YS75000; Part Number: 06-0000017; Price: 0.0083; Vendor: WURTH ELEKTRONIK; Datasheet: https://www.digikey.com/en/products/detail/w%C3%BCrth-elektronik/150060YS75000/4489909
DS3 = LED: Manufacture_Name: WURTH ELEKTRONIK; Manufacture_Part_Number: 150060BS75000; Part Number: 06-0000014; Price: 0.0083; Vendor: WURTH ELEKTRONIK; Datasheet: https://www.digikey.com/en/products/detail/w%C3%BCrth-elektronik/150060BS75000/4489893
JP28 = B2B-PH-K-SLFSN: Manufacture_Name: JST; Part Description: CONN HEADER VERT 2POS 2MM; Part Number: 08-0000044; Datasheet: https://www.jst-mfg.com/product/pdf/eng/ePH.pdf
Q2 Q3 = MMBT3904_SOT: Manufacture_Name: NEXPERIA; Manufacture_Part_Number: PMBT3904-215; Part Number: 06-0000022; Vendor: nexperia; Datasheet: https://www.digikey.com/en/products/detail/nexperia-usa-inc/PMBT3904-215/763515
R19 R27 R30 R66 = SMALL_R1: Manufacture_Name: WALSIN; Manufacture_Part_Number: WR04X1001FTL; Part Description: RES 1K OHM 1% 0402; Part Number: 03-2000028; Price: 0.0002; Vendor: CYNTEC; Datasheet: https://www.digikey.com/en/products/detail/walsin-technology-corporation/WR04X1001FTL/13240628?s=N4IgTCBcDaIOoCUAMAWAGgRiUjAxAKgDIgC6AvkA
R25 R54 R61 R62 R84 R85 R97 R111 = SMALL_R1: Part Number: 03-2000042
R26 = SMALL_R1: Manufacture_Name: YAGEO; Manufacture_Part_Number: RC0402JR-07560RL; Part Number: 03-2000015; Price: 0.0002; Vendor: YAGEO; Datasheet: https://www.digikey.com/en/products/detail/yageo/RC0402JR-07560RL/726492?s=N4IgTCBcDaIEoGEAMAWJYBScC0SDsArAGxJwAyIAugL5A
R28 = SMALL_R1: Manufacture_Name: YAGEO; Manufacture_Part_Number: RC0402JR-07470RL; Part Number: 03-2000012; Price: 0.0002; Vendor: YAGEO; Datasheet: https://www.digikey.com/en/products/detail/yageo/RC0402JR-07470RL/726482?s=N4IgTCBcDaIEoGEAMAWJYBScC0SDsKeScAMiALoC%2BQA
R71 R119 = SMALL_R1: Manufacture_Name: YAGEO; Manufacture_Part_Number: RC0402JR-0710KL; Part Number: 03-2000021; Price: 0.0002; Datasheet: https://www.digikey.com/en/products/detail/yageo/RC0402JR-0710KL/726418
U3 = LIS3DHTR_0: Manufacture_Name: STMicroelectronics; Part Description: ACCEL 2-16G I2C/SPI 16LGA; Part Number: 05-0000003; Price: 0.84; Vendor: ATMOSIC; Datasheet: https://www.digikey.com/en/products/detail/stmicroelectronics/LIS3DH/2334335
U4 = ENS210-LQFM_2: Manufacture_Name: SCIOSENSE; Part Number: 05-0000005; Vendor: SCIOSENSE; Datasheet: https://www.mouser.com/ProductDetail/ScioSense/ENS210-LQFM?qs=Zcin8yvlhnP3xLiFn26B1g%3D%3D
U13 = LM258DRG3_0: Manufacture_Name: PUYA; Manufacture_Part_Number: P25Q16SU-UXH-IR; Part Description: SPI Nor Flash, 4Mbit, 1.65V~3.6V, USON8; Part Number: 05-xxxxxxx; Price: 0.2; Vendor: PUYA
U15 = 24AA014_0
J12 = HEADER_25X2: Manufacture_Name: AMPHENOL ICC (FCI); Manufacture_Part_Number: 67996-150HLF; Part Number: 08-0000004; Vendor: AMPHENOL ICC (FCI); Datasheet: https://www.digikey.com/products/en?keywords=67996-150HLF
DS4 = LED: Manufacture_Name: WURTH ELEKTRONIK; Manufacture_Part_Number: 150060GS75000; Part Number: 06-0000015; Price: 0.0043; Vendor: WURTH ELEKTRONIK; Datasheet: https://www.digikey.com/en/products/detail/w%C3%BCrth-elektronik/150060GS75000/4489898?s=N4IgTCBcDaIIwFYAMSBsSDiBlA7MlIAugL5A
J15 = USB_CONN_1_v2: Manufacture_Name: AMPHENOL ICC (FCI); Part Number: 07-0000004; Vendor: AMPHENOL ICC (FCI); Datasheet: https://www.digikey.com/en/products/detail/amphenol-icc-fci/10118194-0001LF/2785389
J27 = USB_CONN_1
R40 R112 R113 R118 = SMALL_R1: Manufacture_Name: PANASONIC; Manufacture_Part_Number: ERJ-2GE0R00X; Part Number: 03-2000018; Price: 0.0002; Datasheet: https://www.digikey.com/en/products/detail/panasonic-electronic-components/erj-2ge0r00x/146727
R46 R47 = SMALL_R1: Manufacture_Name: YAGEO; Manufacture_Part_Number: RC0402JR-0733RL; Part Number: 03-2000003; Price: 0.0002; Vendor: YAGEO; Datasheet: https://www.digikey.com/en/products/detail/yageo/RC0402JR-0733RL/726467?s=N4IgTCBcDaIDoBcAEAlAwgBgCwbAKRQFoMB2AZjJQBkQBdAXyA
TC1 = TC2030-IDC: Part Number: 08-0000038
U5 = NSP4201MR6_0: Manufacture_Name: onsemi; Manufacture_Part_Number: NSP4201MR6T1G; Part Description: TVS DIODE 5VWM 12VC 6TSOP; Part Number: 05-0000023; Vendor: ATMOSIC; Datasheet: https://www.digikey.com/product-detail/en/on-semiconductor/NSP4201MR6T1G/NSP4201MR6T1GOSCT-ND/7556459
U6 = MK22FN128VLH10_0: Manufacture_Name: NXP; Part Description: IC MCU 32BIT 128KB FLASH 64LQFP; Part Number: 05-0000004; Price: 4.64; Vendor: ATMOSIC; Datasheet: https://www.digikey.com/en/products/detail/nxp-usa-inc/MK22FN128VLH10/4800173
U22 = 54AS00_0: Manufacture_Name: NEXPERIA; Part Description: AND Gate IC 1 Channel SC-74A, 1.65~6.5V; Part Number: 05-0000034; Datasheet: https://www.digikey.com/en/products/detail/nexperia-usa-inc/74lvc1g08gv-125/1231422
BT2 = BAT: Manufacture_Name: MPD; Part Number: 08-0000015; Datasheet: https://www.digikey.tw/zh/products/detail/mpd-memory-protection-devices/BC2032-E2/2077836?s=N4IgTCBcDaIEIGEwAYDMYC0BRCBdAvkA
C50 = SMALL_CAP: Manufacture_Name: TDK; Manufacture_Part_Number: CGA2B2NP01H102J050BA; Part Number: 01-2000005; Price: 0.01; Vendor: TDK; Datasheet: https://www.digikey.com/en/products/detail/tdk-corporation/CGA2B2NP01H102J050BA/3953784
C61 = SMALL_CAP: Manufacture_Name: TDK; Manufacture_Part_Number: CGA2B3X7R1H103K050BB; Part Number: 01-2000001; Price: 0.0016; Vendor: TDK; Datasheet: https://www.digikey.com/en/products/detail/tdk-corporation/CGA2B3X7R1H103K050BB/2672786
FD1-FD4 = TEST_POINT: Part Number: 09-0000007
J22 = HEADER_3: Part Number: 08-0000020; Vendor: AMPHENOL ICC (FCI)
MT1-MT4 = TEST_POINT: Part Number: 09-0000006
R58 = SMALL_R1: Manufacture_Name: YAGEO; Manufacture_Part_Number: RC0402FR-0727KL; Part Number: 03-2000033; Price: 0.0002; Vendor: YAGEO; Datasheet: https://www.digikey.com/en/products/detail/yageo/RC0402FR-0727KL/726574
TP19-TP22 = TP: Manufacture_Name: KEYSTONE ELECTRONICS; Manufacture_Part_Number: 36-5012-ND; Part Number: 08-0000007; Vendor: KEYSTONE ELECTRONICS; Datasheet: https://www.digikey.com/product-detail/en/keystone-electronics/5012/36-5012-ND/255334
VR1 = VAR_REG: Manufacture_Name: DIODES; Part Number: 06-0000020; Vendor: DIODES; Datasheet: https://www.digikey.com/en/products/detail/diodes-incorporated/ap2127k-3-3trg1/4470786
VR2 = VAR_REG: Manufacture_Name: STMICROELECTRONICS; Part Number: 06-0000021; Vendor: STMICROELECTRONICS; Datasheet: https://www.digikey.com/en/products/detail/stmicroelectronics/ldk130m-r/4441191
VR3 = VAR_REG: Manufacture_Name: DIODES; Manufacture_Part_Number: AP2127K-1-8TRG1; Part Number: 06-0000019; Vendor: DIODES; Datasheet: https://www.digikey.com/en/products/detail/diodes-incorporated/AP2127K-1-8TRG1/4470784?s=N4IgTCBcDaIIIAUwEYwHYDSBaZA6AHACoBKA4siALoC%2BQA
Q5 = BSS84_SOT_0: Manufacture_Name: INFINEON; Manufacture_Part_Number: BSS84PWH6327XTSA1; Part Description: PMOS 60 V 150mA (Ta) 300mW (Ta) SOT323; Part Number: 06-0000057; Datasheet: https://www.digikey.com/en/products/detail/infineon-technologies/BSS84PWH6327XTSA1/5410126
R108 = SMALL_R1: Manufacture_Name: YAGEO; Manufacture_Part_Number: RC0402JR-07100KL; Part Number: 03-2000020; Price: 0.0002; Datasheet: https://www.digikey.com/en/products/detail/yageo/RC0402JR-07100KL/726416
R109 = SMALL_R1: Manufacture_Name: YAGEO; Manufacture_Part_Number: RC0402FR-0793K1L; Part Description: RES 93.1K OHM 1% 0402; Part Number: 03-2000071; Price: 0.0002; Datasheet: https://www.digikey.com/en/products/detail/yageo/RC0402FR-0793K1L/5281120?s=N4IgTCBcDaIEoGEAMAWJYBicC0SDsAnAMwDSAjADIgC6AvkA
R110 = SMALL_R1: Manufacture_Name: YAGEO; Manufacture_Part_Number: RC0402JR-0750RL; Part Description: RES 50 OHM 5% 1/16W 0402; Part Number: 03-2000072; Price: 0.0002; Datasheet: https://www.digikey.com/en/products/detail/yageo/RC0402JR-0750RL/5917787?s=N4IgTCBcDaIEoGEAMAWJYBScC0SDsArEnADIgC6AvkA
U17 U19-U21 = MCP6001: Manufacture_Name: Microchip Technology; Manufacture_Part_Number: MCP6001T-E/LT; Part Description: IC OPAMP GP 1 CIRCUIT SOT23-5; Part Number: 05-0000021; Datasheet: https://www.digikey.com/en/products/detail/microchip-technology/MCP6001T-E-LT/683192
U18 = TMUX1237: Manufacture_Name: Texas Instruments; Manufacture_Part_Number: TMUX1237DCKR; Part Description: IC SWITCH SPDT X 1 4.5OHM SC70-6; Part Number: 05-0000022; Datasheet: https://www.digikey.com/en/products/detail/texas-instruments/tmux1237dckr/12165109

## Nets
1.8V: J22.3 R60.2
3.0V: J21.1 J22.1 R57.2
3.3V: C39.2 C40.1 C45.1 J12.26 R26.2 R28.2 R53.2 R109.1 U6.7(USBVDD)
AVDD1: C12.1 C13.1 R6.1 U1.1(AVDD1)
AVDD1P: C4.1 JP5.1 SB9.1 U1.18(AVDD1P)
AVDDPA: J3.2 R13.1
DVDD1: C1.1 JP1.2 SB2.2 U1.21(DVDD1)
DVDD1P: C3.1 JP1.1 SB2.1 U1.20(DVDD1P)
GND_SIGNAL: BT2.2(NEG) C1.2 C2.1 C3.2 C4.2 C5.2 C6.2 C7.2 C10.2 C11.2 C12.2 C13.2 C17.2 C20.1 C21.1 C22.2 C31.2 C32.2 C35.1 C36.2 C37.1 C38.2 C39.1 C40.2 C41.2 C42.2 C43.2 C44.2 C45.2 C46.2 C48.1 C49.1 C51.1 C52.1 C54.1 C55.1 C56.2 C57.2 C58.2 C59.2 C60.2 C61.1 C62.2 C66.2 C67.1 C68.2 C72.2 C74.2 C75.2 DS1.1(CATHODE) J4.2(GND1) J4.3(GND2) J12.1 J12.27 J15.5(GND) J15.S1(CASE) J15.S2(CASE) J15.S3(CASE) J15.S4(CASE) J15.S5(CASE) J15.S6(CASE) J27.5(GND) J27.S1(CASE) J27.S2(CASE) J27.S3(CASE) MT1.1 MT2.1 MT3.1 MT4.1 Q2.2(E) Q3.2(E) R8.1 R15.1 R25.1 R29.1 R45.1 R59.2 R62.2 R72.1 R74.1 R79.1 R98.1 R99.1 R108.2 R111.2 R119.2 S3.3 S3.4 SB6.2 TC1.5(GND) TP3.1(TP) TP4.1(TP) TP5.1(TP) TP23.1(TP) U1.41(EGND) U3.5(GND) U3.10(RES) U3.12(GND_1) U4.4(VSS) U4.5(VSS_1) U5.2(GND) U6.4(VSS) U6.15(VREFL) U6.16(VSSA) U6.31(VSS) U6.32(PTA18) U6.33(PTA19) U6.47(VSS) U7.6(GND) U9.6(GND) U10.6(GND) U11.6(GND) U12.6(GND) U13.4(GND) U13.9(EP) U15.2(VSS) U15.4(A1) U16.6(GND) U17.2 U18.5(S6) U19.2 U20.2 U21.2 U22.3(GND) VR1.2(GND) VR2.2(GND) VR3.2(GND) Y2.2(NC) Y2.4(NC)
VBAT: C7.1 J23.1 J26.1 JP12.1 SB136.1 U1.13(VBAT)
VCC_F: C67.2 R95.1 R96.1 U11.15(1Y1) U13.8(VCC)
VCC_S: C62.1 R20.2 R22.2 R23.1 R24.1 R31.2 R69.2 R71.2 R84.2 R85.2 R97.2 S2.3 S2.4 U10.15(1Y1) U15.6(VCC)
VCC_USB: C49.2 C52.2 C55.2 C75.1 DS4.2(ANODE) J15.1(VBUS) J27.1(VBUS) Q5.2(S) TP21.1(TP) U5.5(VP) U17.5 U18.2(VDD) U19.5 U20.5 U21.5 VR1.1(VIN) VR1.3(EN) VR2.1(VIN) VR2.3(EN) VR3.1(VIN) VR3.3(EN)
VCCIO: C35.2 C36.1 C37.2 C38.1 C56.1 C57.1 C58.1 C59.1 C60.1 C72.1 J12.2 J12.50 J26.3 JP8.1 JP11.1 JP25.1 JP27.1 JP28.1 R78.2 R104.2 R113.2 U7.14(VCC) U9.14(VCC) U10.14(VCC) U11.14(VCC) U12.14(VCC) U16.14(VCC)
VCCIO_K22: C41.1 C42.1 C43.1 C44.1 JP14.1 SB138.1 TC1.1(VCC) U6.3(VDD) U6.13(VDDA) U6.14(VREFH) U6.21(VBAT) U6.26(PTA4/LLWU_P3) U6.30(VDD) U6.48(VDD) U22.5(VCC)
VDDIO: C10.1 C11.1 JP13.1 JP24.1 R112.1 SB137.1 U1.6(VDDIO) U1.28(VDDIO)
VDDIO_FLASH: JP16.1 SB141.1 U11.16(1Z)
VDDIO_SENS: JP15.1 SB140.1 U10.16(1Z)
VDDIOP: C6.1 J3.1 J23.3 JP26.2 U1.17(VDDIOP)
VDDPAP: C2.2 C68.1 J3.3 U1.15(VDDPAP)
BBOOT: R118.1 U9.1(1Y0)
BENIGN_BOOT: R66.1 R119.1 U22.1(A)
BUTTON_1: JP28.2 R29.2 S2.1 S2.2 SB131.2
BUTTON_2: R31.1 S3.1 S3.2 U16.15(1Y1)
DM: R46.1 U6.6(USB0_DM)
DP: R47.1 U6.5(USB0_DP)
FLASH_CS_L: R95.2 U11.7(3Y1) U13.1(CS#)
FLASH_RESET_L: R96.2 U11.3(2Y1) U13.7(RESET#)
FLASH_SCLK: U11.11(4Y1) U13.6(SCLK)
FLASH_SIO0: U12.3(2Y1) U13.5(SI/SIO0)
FLASH_SIO1: U12.7(3Y1) U13.2(SO/SIO1)
FLASH_SIO2: U12.11(4Y1) U13.3(WP#/SIO2)
G_INT: U3.11(INT1) U10.11(4Y1)
I2C0_SCK: R71.1 R97.1 U3.4(SCL/SPC) U4.2(SCL) U10.7(3Y1) U15.1(SCL)
I2C0_SDA: R69.1 R84.1 U3.6(SDA/SDI/SDO) U4.3(SDA) U10.3(2Y1) U15.3(SDA)
LED_1: R19.2 U16.3(2Y1)
LED_2: R27.1 U16.7(3Y1)
LED_3: R30.1 U16.11(4Y1)
NO_K22: JP11.2 R74.2 R83.1 SB143.1 U7.2(S)
P0: J12.32 U1.4(P0) U9.4(2Z)
P1: J12.33 U1.5(P1) U9.8(3Z)
P3: J12.35 U1.7(P3) U16.16(1Z)
P4: J12.36 U1.8(P4) U10.8(3Z)
P5: J12.37 SB131.1 U1.9(P5)
P6: J12.38 U1.10(P6) U16.8(3Z)
P7: J12.39 U1.11(P7) U16.4(2Z)
P12: J12.4 U1.24(P12) U7.12(4Z)
P13: J12.5 U1.25(P13) U7.16(1Z)
P14: J12.6 U1.26(P14) U10.12(4Z)
P15: J12.7 U1.27(P15) U7.4(2Z)
P17: J12.9 U1.29(P17) U11.4(2Z)
P18: J12.10 U1.30(P18) U11.12(4Z)
P19: J12.11 U1.31(P19) U11.8(3Z)
P20: J12.12 U1.32(P20) U12.4(2Z)
P21: J12.13 U1.33(P21) U12.8(3Z)
P22: J12.14 U1.34(P22) U12.12(4Z)
P25: J12.17 R15.2 R107.2 U1.35(P25) U9.16(1Z)
P27: J12.22 U1.38(P27) U9.12(4Z)
P29: J12.24 U1.39(P29) U10.4(2Z)
P30: J12.25 U1.40(P30) U7.8(3Z)
PWD: J12.49 R8.2 R67.1 S1.1 S1.2 U1.12(PWD)
RFIO: L11.2 U1.2(RFIO)
SWDCLK_K22: R39.1 U9.5(2Y0)
SWDIO_K22: R38.1 U9.9(3Y0)
UART0_CTS_K22: R51.1 U7.13(4Y0)
UART0_RTS_K22: R50.1 U7.1(1Y0)
UART0_RX_K22: R48.1 U7.9(3Y0)
UART0_TX_K22: R49.1 U7.5(2Y0)
UART1_CTS_K22: R43.1 TP7.1(TP)
UART1_RTS_K22: R42.1 TP6.1(TP)
UART1_RX_K22: R40.1 U22.2(B)
UART1_TX_K22: R41.1 U9.13(4Y0)
UART2_CTS_K22: TP11.1(TP) U6.44(PTC1/LLWU_P6)
UART2_RTS_K22: TP10.1(TP) U6.45(PTC2)
UART2_RX_K22: TP8.1(TP) U6.49(PTC4/LLWU_P8)
UART2_TX_K22: TP9.1(TP) U6.46(PTC3/LLWU_P7)
USB_D+: J15.3(D+) J27.3(D+) R47.2 U5.3(IO2) U5.4(IO3)
USB_D-: J15.2(D-) J27.2(D-) R46.2 U5.1(IO1) U5.6(IO4)
USE_FLASH: JP8.2 R79.2 U11.2(S) U12.2(S)
VAUX: C5.1 JP26.1 U1.19(VAUX)
VCOINCELL: BT2.1(POS) J21.3 R104.1
XTALI_16M: U1.37(XTALO_16M) Y2.1(HOT)
XTALI_32K: SB6.1 U1.23(XTALI_32K) Y1.2
XTALO_16M: U1.36(XTALI_16M) Y2.3(HOT)
XTALO_32K: U1.22(XTALO_32K) Y1.1
N16735640: JP5.2 R6.2 SB9.2
N16873328: L1.1 U1.14(LEXT1)
N16873338: L1.2 U1.16(LEXT2)
N16893506: C17.1 R13.2 U1.3(VDDPA)
N17095028: C47.2 C48.2 R53.1 R54.1 VR1.5(VOUT)
N17095050: C47.1 C61.2 R54.2 VR1.4(ADJ)
N17095106: J21.2 JP12.2 R73.1 SB136.2
N17095108: J23.2 JP13.2 JP15.2 JP16.2 R77.2 SB137.2 SB140.2 SB141.2
N17095279: C53.2 C54.2 R60.1 R61.1 VR3.5(VOUT)
N17095319: C53.1 R61.2 R62.1 VR3.4(ADJ)
N17095531: C50.2 C51.2 R57.1 R58.1 VR2.5(VOUT)
N17095557: C50.1 R58.2 R59.1 VR2.4(ADJ)
N17096185: J22.2 JP14.2 JP24.2 R78.1 SB138.2 TP20.1(TP)
N17100046: R99.2 SB143.2 TP24.1(TP) U9.2(S)
N17100334: JP25.2 R72.2 U10.2(S)
N17102737: DS1.2(ANODE) R19.1
N17102803: C31.1 R20.1 U3.1(VDD_IO) U3.14(Vdd)
N17102805: C32.1 R22.1 U4.1(VDD)
N17102917: DS2.2(ANODE) R26.1
N17102919: DS2.1(CATHODE) Q2.3(C)
N17103005: R23.2 R25.2 U3.7(SDO/SA0)
N17103017: Q2.1(B) R27.2
N17103021: R24.2 U3.8(CS)
N17103073: DS3.2(ANODE) R28.1
N17103075: DS3.1(CATHODE) Q3.3(C)
N17103123: Q3.1(B) R30.2
N17103574: R85.1 U15.5(A0)
N17105483: R67.2 U6.2(PTE1/LLWU_P0)
N17105496: R83.2 TP15.1(TP) U6.58(PTD1)
N17105530: R38.2 U6.63(PTD6/LLWU_P15)
N17105555: R39.2 U6.62(PTD5)
N17105589: R66.2 U6.61(PTD4/LLWU_P14)
N17105614: R40.2 U6.60(PTD3)
N17105656: R41.2 U6.59(PTD2/LLWU_P13)
N17105670: R42.2 U6.54(PTC9)
N17105708: R43.2 U6.53(PTC8)
N17105834: DS4.1(CATHODE) R45.2
N17106014: R48.2 U6.40(PTB17)
N17106031: R49.2 U6.39(PTB16)
N17106052: R50.2 U6.38(PTB3)
N17106071: R51.2 U6.37(PTB2)
N17106085: C46.1 TC1.3(NRESET) U6.34(RESET_B)
N17106116: TC1.4(SWCLK) U6.22(PTA0)
N17106118: TC1.6(SWO) U6.24(PTA2)
N17106120: TC1.2(SWDIO) U6.25(PTA3)
N17109714: J26.2 S1.3 S1.4
N17114657: JP27.2 R98.2 U16.2(S)
N17183908: R107.1 U16.12(4Z)
N17231398: R108.1 R109.2 U17.3
N17231411: U18.1(S2) U19.3 U20.1 U20.4
N17231419: U18.6(SEL) U19.1
N17231425: U17.1 U17.4 U18.3(S1) U19.4
N17231518: Q5.3(D) R111.1 R113.1 U21.3
N17231524: R112.2 U20.3
N17231536: Q5.1(G) U21.1
N17231553: R110.2 U18.4(D)
N17231555: C74.1 R110.1 U21.4
N17231767: R118.2 U22.4(Y)
N17319836: R77.1 TP19.1(TP)
N17319837: R73.2 TP22.1(TP)
N17320329: TP14.1(TP) U6.57(PTC0/LLWU_P12)
N17320330: TP13.1(TP) U6.56(PTC11/LLWU_P11)
N17320331: TP16.1(TP) U6.64(PTD7)
N17327104: C18.2 J4.1(IO)
N17327106: C18.1 C65.2 C66.1 L3.1
N17327116: C20.2 C65.1 L12.1
N17327122: C21.2 L11.1 L12.2
N17327180: C22.1 L3.2

Not connected (* = marked no-connect by the designer): FD1 1*; FD2 1*; FD3 1*; FD4 1*; J12 3* 8* 15* 16* 18* 19* 20* 21* 23* 28* 29* 30* 31* 34* 40* 41* 42* 43* 44* 45* 46* 47* 48*; J15 4(IO)*; J27 4(IO)*; U3 2(NC)* 3(NC_1)* 9(INT2)* 13(ADC3)* 15(ADC2)* 16(ADC1)*; U6 1(PTE0/CLKOUT32K)* 8(NC)* 9(ADC0_DP0/ADC1_DP3)* 10(ADC0_DM0/ADC1_DM3)* 11(ADC1_DP0/ADC0_DP3)* 12(ADC1_DM0/ADC0_DM3)* 17(VREF_OUT)* 18(DAC0_OUT)* 19(XTAL32)* 20(EXTAL32)* 23(PTA1)* 27(PTA5)* 28(PTA12)* 29(PTA13/LLWU_P4)* 35(PTB0/LLWU_P5)* 36(PTB1)* 41(PTB18)* 42(PTB19)* 43(PTC0)* 50(PTC5/LLWU_P9)* 51(PTC6/LLWU_P10)* 52(PTC7)* 55(PTC10)*; U7 3(2Y1)* 7(3Y1)* 10(N_C_)* 11(4Y1)* 15(1Y1)*; U9 3(2Y1)* 7(3Y1)* 10(N_C_)* 11(4Y1)* 15(1Y1)*; U10 1(1Y0)* 5(2Y0)* 9(3Y0)* 10(N_C_)* 13(4Y0)*; U11 1(1Y0)* 5(2Y0)* 9(3Y0)* 10(N_C_)* 13(4Y0)*; U12 1(1Y0)* 5(2Y0)* 9(3Y0)* 10(N_C_)* 13(4Y0)* 15(1Y1)* 16(1Z)*; U16 1(1Y0)* 5(2Y0)* 9(3Y0)* 10(N_C_)* 13(4Y0)*

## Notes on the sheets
sheet 1
- VDDIO < 1.72V: VCCIO = 1.71V
  VDDIO >=1.72V: VCCIO = VDDIO
- Remove R112 when
  using Interface Board
- Remove R113 when
  using Interface Board
- ATMOSIC TECHNOLOGIES INC
sheet 2
- ATM3405 EVALUATION BOARD (with J-Link OB)
- Release Date
- Revision
- Design Eng.
- Design Notes
- 8/04/23
- -00
- Andy Dao
- Initial release, based on the V3.1 Paris 5x5 EVB, with VDDIO-VCCIO tracking circuit added
- 12/07/23
- -10
- Joe Chen
- Add R119 10Kohm(0402) to pull down the BENIGN_BOOT signal.
- 6/04/24
- -20
- Joe Chen
- 1. Changed pin 15 of ATM3405 from VSTORE to VDDPAP
- 2. Replace R8 from 1Mohm to 10Kohm.
- 3. Modify the RFIO matching components
- 4. Remove SB144.
- 5. Modify J3 from "DNS(HDR1X3)" to "HEADER-3".
- 6. Modify J22 from "HEADER-3" to "DNS(HDR1X3)".
- 5/27/25
- -34
- Andy Dao
- 1. Changed RFIO caps back to Johanson (from Murata)
- 2. Added connector (JP28) to support Antenna Diversity daughtercard
- 3. Changed Flash (U13) and analog switches (U11, U12) to DNS
- 4. Grounded VDDPAP; changed  AVDD1, and VDDIOP cap values for best channel sounding performance
- 9/29/25
- -37
- Andy Dao
- 1. Changed C5 and C6 from 4.7uF to 10uF
- Atmosic Technologies, Inc
- 2130 Gold Street, Suite 200
  San Jose, CA 95002
- ATMOSIC TECHNOLOGIES INC
- Atmosic Technologies Proprietary and Confidential
sheet 3
- Block Diagram
- LEDs
- Buttons
- Sensors
- Programming
  Pads
- Power Supplies
- MK22
- USB
  Connector
- Analog
  Switches
- Flash
- BLE Tx/Rx
  Match
- SMA Conn
- 50-pin
  Connector
- Power Supplies
- ATM3405
- Reset Button
- Antenna
  Control
- ATMOSIC TECHNOLOGIES INC
sheet 4
- 16MHz XTAL
- 5X5 QFN
- Power down switch
- PTS645 SMD
- Benign boot
- ATMOSIC TECHNOLOGIES INC
- Atmosic Technologies Proprietary and Confidential
sheet 5
- GPIO MUX
- CONNECT SENSORS TO ATM3405
- ISOLATE MK22 FROM ATM3405
- CONNECT FLASH TO ATM3405
- Install to
  connect Sensors
- Install to
  isolate MK22
- Install to
  connect Flash
- CONNECT LEDS/BUTTONS TO ATM3405
- Assert to
  isolate MK22
- Install to
  connect LEDs
  and Buttons
- ATMOSIC TECHNOLOGIES INC
- Atmosic Technologies Proprietary and Confidential
sheet 6
- BLE front-end match
- Note:
  For inductors, use MHQ series from TDK.
  For capacitors, use Johanson
- RFIO
- ESD150-B1-W0201
- ATMOSIC TECHNOLOGIES INC
- Atmosic Technologies Proprietary and Confidential
sheet 7
- MOTION SENSOR
- LEDS
- BIDS (1Kbits)
- SA0: I2C less significant bit of the device address.
  High: 0x19
  Default: input with internal pull-up
- The I2C slave device address: 0x51
- TEMP/HUM SENSOR
- 24AA014
- PUSH BUTTONS
- The I2C slave device address of ENS210: 0x43
- Antenna Board Control
- FLASH (Reserved)
- PTS645 SMD
- PTS645 SMD
- USON 2x3mm
- ATMOSIC TECHNOLOGIES INC
sheet 8
- SENSOR HUB 50-PIN CONNECTOR
- ATMOSIC TECHNOLOGIES INC
sheet 9
- USB ESD
- (Benign Boot
       /
     UART1_RX)
- Pull-down resistor added because the signal
  could not be forced LOW when MK22 is not active
- 90 OHM DIFF PAIR
- USB
- USB OPTION
- J-Link OB
  Programming Pads
- ATMOSIC TECHNOLOGIES INC
sheet 10
- VCC_USB
- Supply for MK22 USB
- VBATT
- VDDIO
- On-Board Voltage Regulators
- For current
  measurements
- Supply for VCCIO
- Supply for VBAT
  and/or VCCIO
- For current
  measurements
- VCCIO
- BOARD FIDUCIALS
- MOUNTING HOLES
- ATMOSIC TECHNOLOGIES INC
